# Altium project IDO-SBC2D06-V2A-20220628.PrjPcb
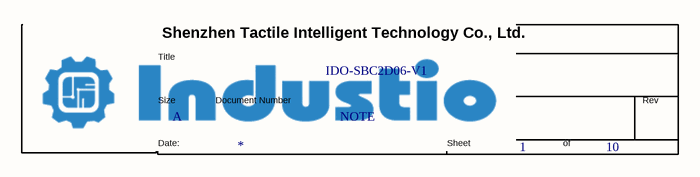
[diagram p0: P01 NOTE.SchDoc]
10 sheets, 212 parts. Net scope: global (net labels, ports and power ports of the same name join across sheets).
Sheets:
  P01 NOTE.SchDoc
  P02 POWER TREE.SchDoc
  P03 BLOCK.SchDoc
  P04 POWER_SUPPLY.SchDoc
  P06 USB_SD.SchDoc
  P07 ETHERNET.SchDoc
  P08 LCD_TP.SchDoc
  P09 AUDIO.SchDoc
  P10 Debug_RS485_RS232.SchDoc
  P05 2D02.SchDoc

## Sheet P01 NOTE.SchDoc
size 420 x 297 mm

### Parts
(Parts that share a designator on the sheet are numbered #1, #2 ... from top to bottom, then left to right.)
*#1  Page Count: 10  Page Number: 1  Page Size: A  Title: IDO-SBC2D06-V1  Doc: NOTE  (hidden comment: TitleBlock1)  (graphical)

## Sheet P02 POWER TREE.SchDoc
size 420 x 297 mm
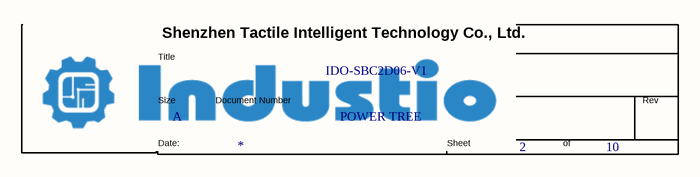
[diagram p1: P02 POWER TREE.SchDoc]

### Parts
(Parts that share a designator on the sheet are numbered #1, #2 ... from top to bottom, then left to right.)
*#2  Page Count: 10  Page Number: 2  Page Size: A  Title: IDO-SBC2D06-V1  Doc: POWER TREE  (hidden comment: TitleBlock1)  (graphical)

## Sheet P03 BLOCK.SchDoc
size 420 x 297 mm
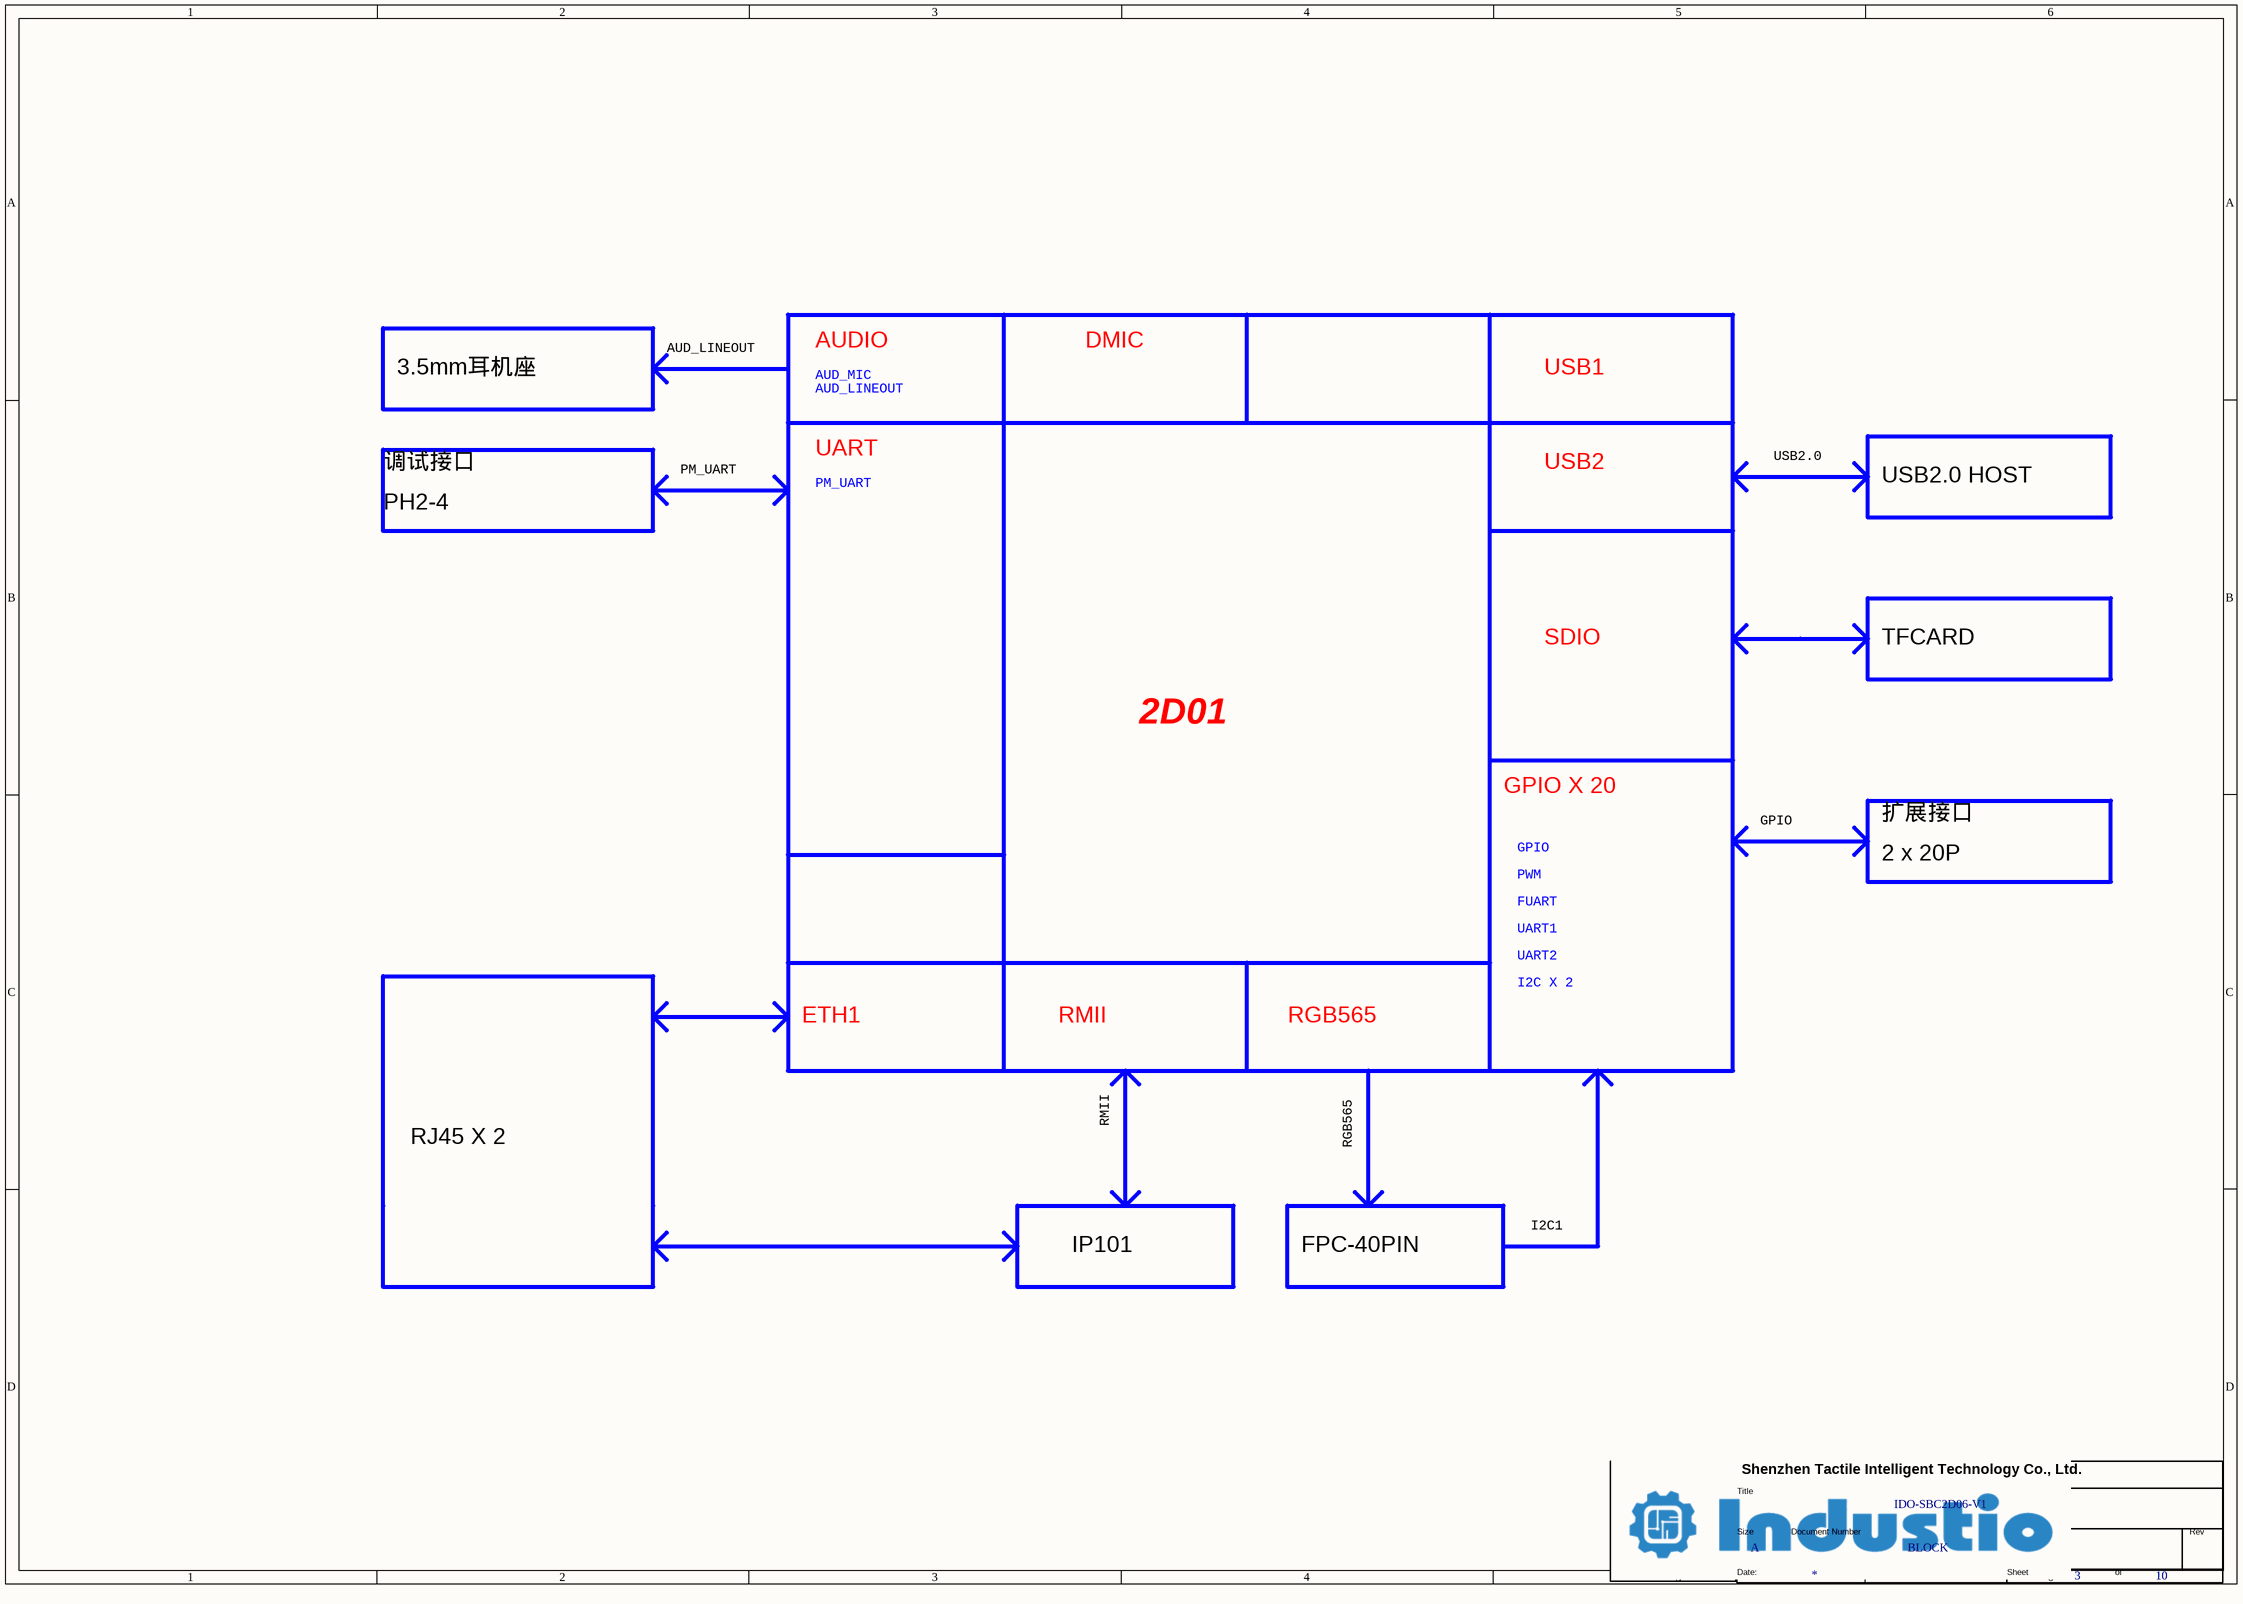
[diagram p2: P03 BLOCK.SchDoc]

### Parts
(Parts that share a designator on the sheet are numbered #1, #2 ... from top to bottom, then left to right.)
*#3  Page Count: 10  Page Number: 3  Page Size: A  Title: IDO-SBC2D06-V1  Doc: BLOCK  (hidden comment: TitleBlock1)  (graphical)

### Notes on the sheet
- 3.5mm耳机座
- AUD_LINEOUT
- AUDIO
- AUD_MIC
- DMIC
- USB1
- UART
- USB2.0
- 调试接口
- PH2-4
- PM_UART
- USB2
- USB2.0 HOST
- SDIO
- TFCARD
- 2D01
- GPIO X 20
- GPIO
- 扩展接口
- 2 x 20P
- PWM
- FUART
- UART1
- I2C X 2
- UART2
- ETH1
- RMII
- RGB565
- RJ45 X 2
- IP101
- FPC-40PIN
- I2C1

## Sheet P04 POWER_SUPPLY.SchDoc
size 420 x 297 mm
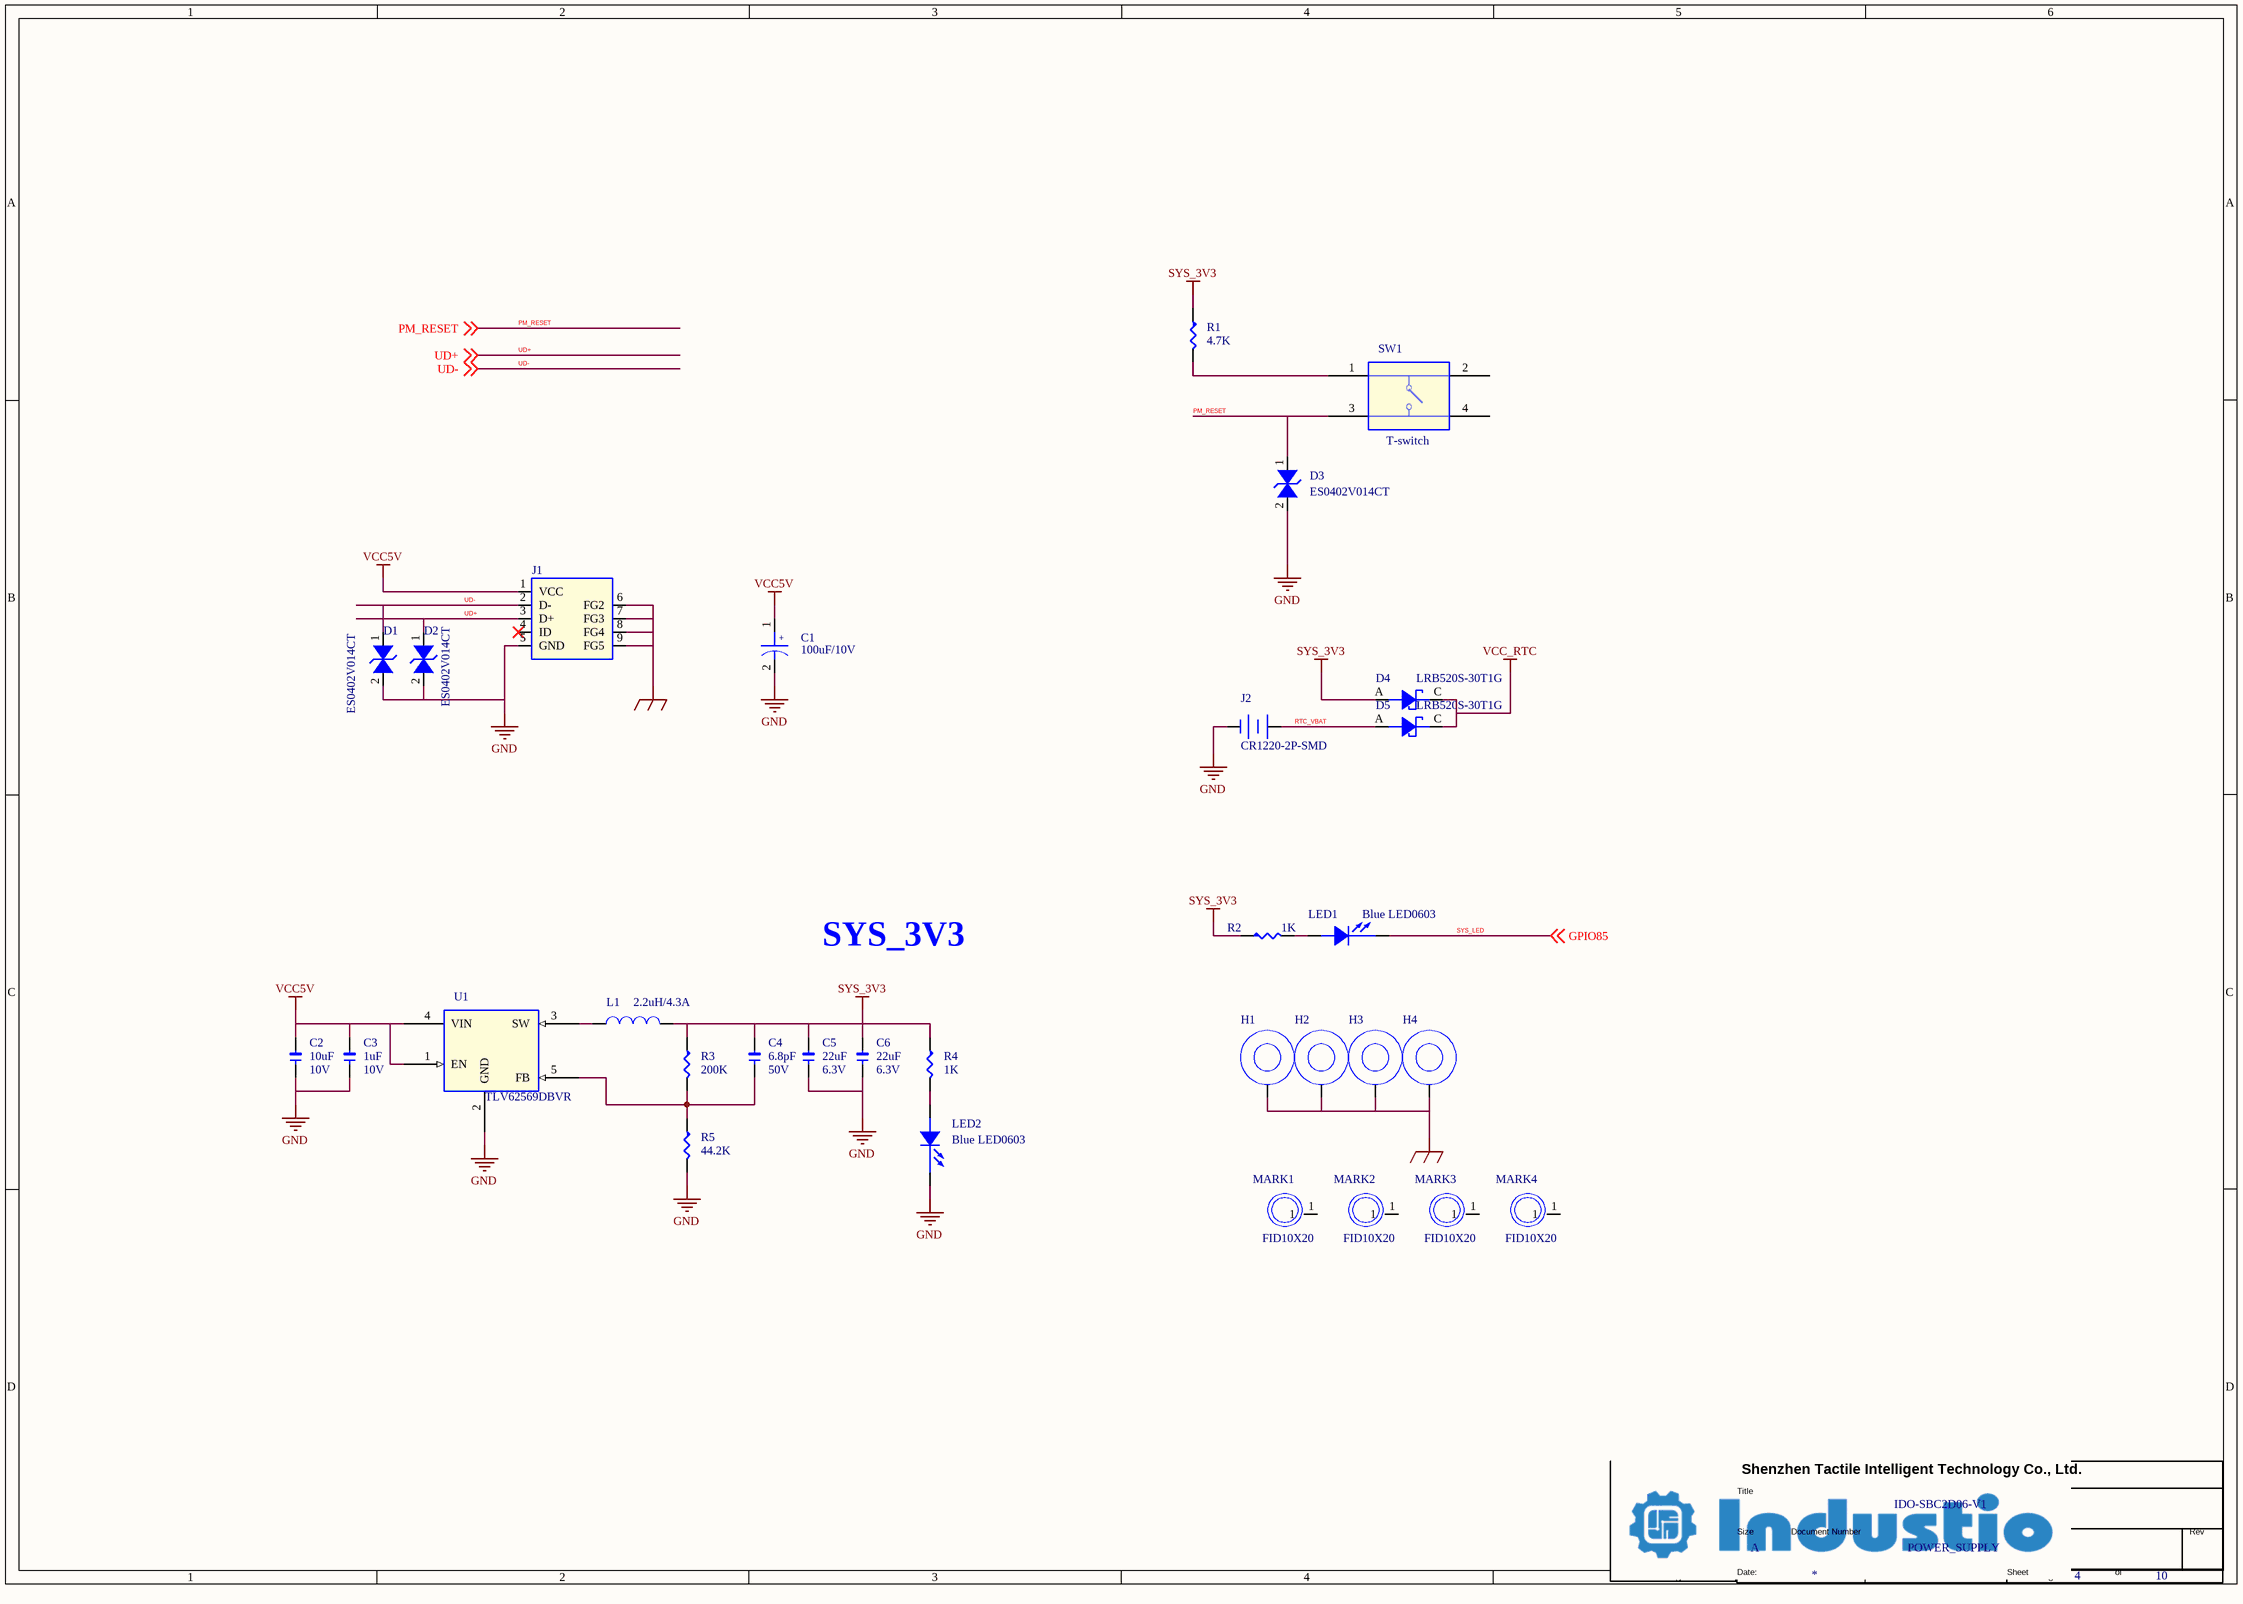
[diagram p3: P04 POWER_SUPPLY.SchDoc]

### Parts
(Parts that share a designator on the sheet are numbered #1, #2 ... from top to bottom, then left to right.)
*#4  Page Count: 10  Page Number: 4  Page Size: A  Title: IDO-SBC2D06-V1  Doc: POWER_SUPPLY  (hidden comment: TitleBlock1)  (graphical)
C1  100uF/10V  [CAPAE530X540]
C2  10uF  DSC2: 10V  [1206]
C3  1uF  DSC2: 10V  [1206]
C4  6.8pF  DSC2: 50V  [1206]
C5  22uF  DSC2: 6.3V  [1206]
C6  22uF  DSC2: 6.3V  [1206]
D1  ES0402V014CT  [V0402]
D2  ES0402V014CT  [V0402]
D3  ES0402V014CT  [V0402]
D4  LRB520S-30T1G  [SOD523]
D5  LRB520S-30T1G  [SOD523]
H1  HOLE  [MTG300_600]  (value not drawn)
H2  HOLE  [MTG300_600]  (value not drawn)
H3  HOLE  [MTG300_600]  (value not drawn)
H4  HOLE  [MTG300_600]  (value not drawn)
J1  MicroUSB  [MICROUSB-5SB]  (value not drawn)
J2  CR1220-2P-SMD  [CR1220-2P-SMD]
L1  2.2uH/4.3A  [L4040]
LED1  Blue LED0603  [LED0603]
LED2  Blue LED0603  [LED0603]
MARK1  FID10X20  [MARK]
MARK2  FID10X20  [MARK]
MARK3  FID10X20  [MARK]
MARK4  FID10X20  [MARK]
R1  4.7K  [R0402L]
R2  1K  [R0402L]
R3  200K  [R0402L]
R4  1K  [R0402L]
R5  44.2K  [R0402L]
SW1  T-switch  [PB-4P-S-4_5x4_5]
U1  TLV62569DBVR  [SOT23-5]

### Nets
GND: C1.2 C2.1 C3.1 C5.1 C6.1 D1.2(I/O1) D2.2(I/O1) D3.2(I/O1) J1.5(GND) J2.2(-) LED2.C(CATHODE) R5.2 U1.2(GND)
GND_EARTH: H1.1 H2.1 H3.1 H4.1 J1.6(FG2) J1.7(FG3) J1.8(FG4) J1.9(FG5)
SYS_3V3: C4.2 C5.2 C6.2 D4.A L1.2 R1.1 R2.1 R3.1 R4.1
VCC5V: C1.1 C2.2 C3.2 J1.1(VCC) U1.1(EN) U1.4(VIN)
VCC_RTC: D4.C D5.C
GPIO85: LED1.C(CATHODE) ; off-sheet GPIO85  [also labelled SYS_LED]
PM_RESET: D3.1(I/O2) SW1.3 ; off-sheet PM_RESET
RTC_VBAT: D5.A J2.1(+)
UD+: D2.1(I/O2) J1.3(D+) ; off-sheet UD+
UD-: D1.1(I/O2) J1.2(D-) ; off-sheet UD-
NetC4_1: C4.1 R3.2 R5.1 U1.5(FB)
NetL1_1: L1.1 U1.3(SW)
NetLED1_A: LED1.A(ANODE) R2.2
NetLED2_A: LED2.A(ANODE) R4.2
NetR1_2: R1.2 SW1.1

Not connected (* = marked no-connect by the designer): J1 4(ID)*; MARK1 1; MARK2 1; MARK3 1; MARK4 1; SW1 2 4

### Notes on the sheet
- SYS_3V3

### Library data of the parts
C1 = C-AL-SMD: Part Number: C020302140004; Part Name: 贴片铝电容; Manufacture: 先科¦立隆¦三莹; DSC1: ±20%; DSC2: 10V; DSC3: 低阻抗; DSC4: 2000H; DSC5: -55~105 ℃; DSC6: SMD,5x5.4mm; DSC7: LZ1A101M-CRD54(ST); ID: 4
C2 = C-0603: Part Number: C020102120071; Part Name: 贴片电容; Manufacture: 三星¦国巨¦村田; ERP Number: 1010200076; DSC1: ±20%; DSC3: X5R; ID: 71; PCB Footprint: C0603L
C3 = C-0402: Part Number: C020102120064; Part Name: 贴片电容; Manufacture: 三星¦国巨¦村田; ERP Number: 1010200054; DSC1: ±10%; DSC3: X5R; ID: 64; PCB Footprint: C0402L
C4 = C-0402: Manufacture: 三星¦国巨¦村田; Part Name: 贴片电容; Part Number: C020102120018; ID: 18; DSC3: C0G; DSC1: ±0.25PF; ERP Number: 1010200056; PCB Footprint: C0402L
C5 C6 = C-0603: Manufacture: 三星¦国巨¦村田; Part Name: 贴片电容; Part Number: C020102120072; ID: 72; DSC3: X5R; DSC1: ±20%; ERP Number: 1010200133; PCB Footprint: C0603L
D1-D3 = DI-ESD: ESD 0402; Manufacturer: INPAQ; Manufacture P/N: MLVG04021R0UV18; Part Number: C040502250002; Manufacture: AEM; PN Type: Varistor; ERP Number: 1010800023; DSC1: 双向; DSC2: Vdc=14V; DSC3: Vbr=300V; DSC4: Vc=30V; DSC5: Cj=0.25pF; ID: 2
D4 D5 = DI-XI-S: Manufacture: 乐山无线电; Part Name: 肖特基二级管; Part Number: C040202220002; CLASS: IC; Solder: 推荐; ID: 2; DSC4: IR=0.5uA; DSC3: VF=350mV/10mA; DSC2: IF=200mA; DSC1: VR=30V
J1 = J-MicroUSB_0: Part Name: USB连接器; Part Number: J060102960001; ID: 1; DSC4: U-F-M5DD-Y-L(韩荣); DSC3: 卧贴; DSC2: 7.6*5.6mm; DSC1: MicroUSB 5S B TYPE 四脚全插牛角型短针 耐高温
J2 = RTC-CR1220-2P-SMD: Part Number: J100303030001; Part Name: 电池座; ERP Number: 1040100045; DSC1: CR1220电池座 贴片 双定位柱; DSC3: 贴片; ID: 4
L1 = L-IND: Part Name: 功率电感; Part Number: C060202340020; Manufacture: 顺络; ERP Number: 1010200404; DSC1: ±20%; DSC2: Isat=6.1A; DSC3: Irms=4.3A; DSC4: 48mΩ; DSC5: 4.0*4.0*2.0mm; DSC6: WPN4020H2R2MT(顺络); ID: 20
LED1 LED2 = D-LED0603: Part Number: C140202660004; Part Name: LED; ERP Number: 1010200068; DSC1: 蓝色LED，SMD,0603，VF=3V; DSC2: NCD0603B1(国星光电); DSC3: 19-217/BHC-ZL1M2RY/3T(亿光); ID: 8
MARK1-MARK4 = MTG240_600_NPH_0: DSC2: 孔径2.4mm; DSC1: 禁止布线层直径=6mm; Type Name: 无铜固定孔; ID: 11
R1 = R-0402: Part Number: C011002080818; Part Name: 贴片电阻; ID: 818; DSC2: 1/16W; DSC1: ±1%; ERP Number: 1010200445
R2 R4 = R-0402: Part Number: C011002080742; Part Name: 贴片电阻; ID: 742; DSC2: 1/16W; DSC1: ±1%; ERP Number: 1010200113
R3 = R-0402: Part Name: 贴片电阻; Part Number: C011002081009; ERP Number: 1010200139; DSC1: ±1%; DSC2: 1/16W; ID: 1,009
R5 = R-0402: Part Name: 贴片电阻; Part Number: C011002080931; ERP Number: 1010200256; DSC1: ±1%; DSC2: 1/16W; ID: 931
SW1 = SW-TS4550TP: Part Name: 轻触开关; Part Number: C180102690001; ID: 1; DSC4: TS-1009S-05026(讯普); DSC3: TS4550TP(首韩); DSC2: SMD,4.5*4.5*5mm; DSC1: 轻触开关,四脚贴片,立贴
U1 = U-TLV62569DBVR: Manufacture: TI; Part Number: C070202410003; Part Name: DCDC; ID: 3; Solder: 推荐; DSC7: 同步降压 轻载效率 低Iq; DSC6: 1.5MHz; DSC5: 0.95; DSC4: Vfb=0.6V; DSC3: Io=2A; DSC2: Vo=0.6-5.5V; DSC1: Vi=2.5-5.5V

## Sheet P06 USB_SD.SchDoc
size 420 x 297 mm
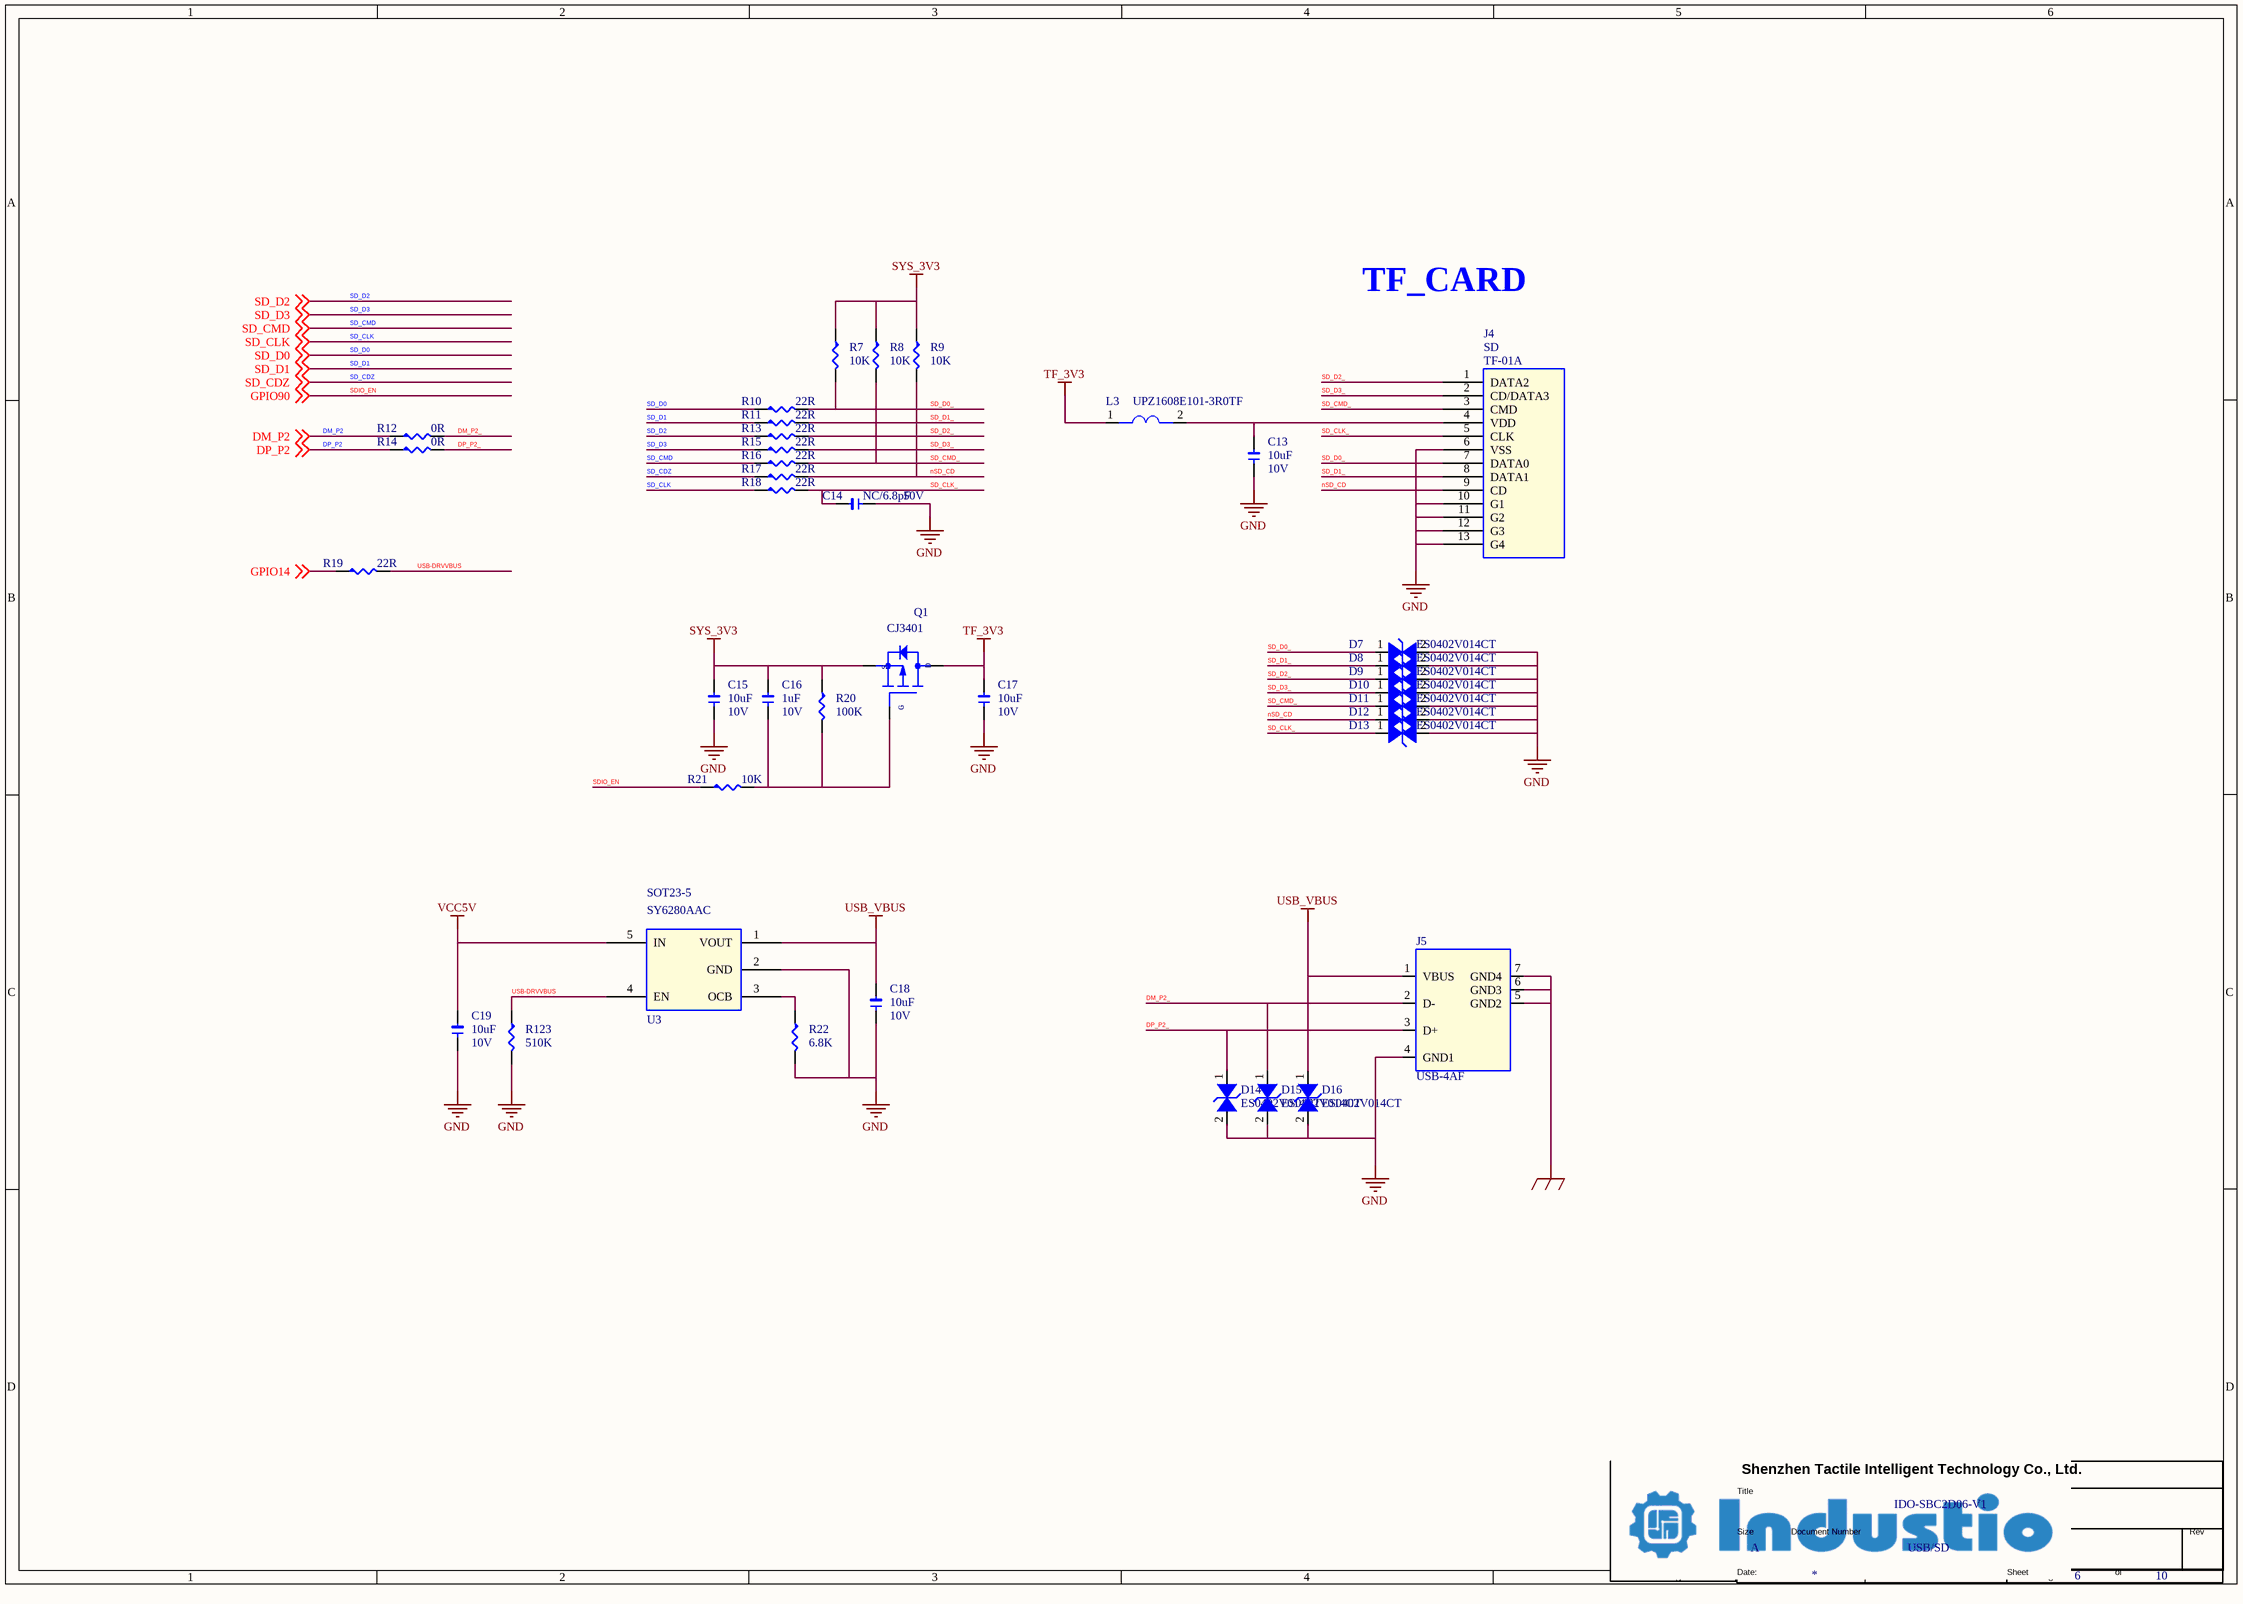
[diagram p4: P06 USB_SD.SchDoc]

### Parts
(Parts that share a designator on the sheet are numbered #1, #2 ... from top to bottom, then left to right.)
*#5  Page Count: 10  Page Number: 6  Page Size: A  Title: IDO-SBC2D06-V1  Doc: USB/SD  (hidden comment: TitleBlock1)  (graphical)
C13  10uF  DSC2: 10V  [1206]
C14  NC/6.8pF  DSC2: 50V  [1206]
C15  10uF  DSC2: 10V  [1206]
C16  1uF  DSC2: 10V  [1206]
C17  10uF  DSC2: 10V  [1206]
C18  10uF  DSC2: 10V  [1206]
C19  10uF  DSC2: 10V  [1206]
D7  ES0402V014CT  [V0402]
D8  ES0402V014CT  [V0402]
D9  ES0402V014CT  [V0402]
D10  ES0402V014CT  [V0402]
D11  ES0402V014CT  [V0402]
D12  ES0402V014CT  [V0402]
D13  ES0402V014CT  [V0402]
D14  ES0402V014CT  [V0402]
D15  ES0402V014CT  [V0402]
D16  ES0402V014CT  [V0402]
J4  SD  [TF-01A]
J5  USB-4AF  [USB-4AF-DIP-3W]
L3  UPZ1608E101-3R0TF  [L0603]
Q1  CJ3401  [SOT23]
R7  10K  [R0402L]
R8  10K  [R0402L]
R9  10K  [R0402L]
R10  22R  [R0402L]
R11  22R  [R0402L]
R12  0R  [R0402L]
R13  22R  [R0402L]
R14  0R  [R0402L]
R15  22R  [R0402L]
R16  22R  [R0402L]
R17  22R  [R0402L]
R18  22R  [R0402L]
R19  22R  [R0402L]
R20  100K  [R0402L]
R21  10K  [R0402L]
R22  6.8K  [R0402L]
R123  510K  [R0402L]
U3  SY6280AAC  [SOT23-5]

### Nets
GND: C13.1 C14.1 C15.1 C17.1 C18.1 C19.1 D7.2(I/O1) D8.2(I/O1) D9.2(I/O1) D10.2(I/O1) D11.2(I/O1) D12.2(I/O1) D13.2(I/O1) D14.2(I/O1) D15.2(I/O1) D16.2(I/O1) J4.6(VSS) J4.10(G1) J4.11(G2) J4.12(G3) J4.13(G4) J5.4(GND1) R22.2 R123.2 U3.2(GND)
GND_EARTH: J5.5(GND2) J5.6(GND3) J5.7(GND4)
SYS_3V3: C15.2 C16.2 Q1.2(SOURCE) R7.1 R8.1 R9.1 R20.1
TF_3V3: C17.2 L3.1 Q1.3(DRAIN)
USB_VBUS: C18.2 D16.1(I/O2) J5.1(VBUS) U3.1(VOUT)
VCC5V: C19.2 U3.5(IN)
DM_P2: R12.1 ; off-sheet DM_P2
DM_P2_: D15.1(I/O2) J5.2(D-) R12.2
DP_P2: R14.1 ; off-sheet DP_P2
DP_P2_: D14.1(I/O2) J5.3(D+) R14.2
GPIO14: R19.1 ; off-sheet GPIO14
GPIO90: R21.1 ; off-sheet GPIO90  [also labelled SDIO_EN]
nSD_CD: D12.1(I/O2) J4.9(CD) R9.2 R17.2
SD_CDZ: R17.1 ; off-sheet SD_CDZ
SD_CLK: R18.1 ; off-sheet SD_CLK
SD_CLK_: C14.2 D13.1(I/O2) J4.5(CLK) R18.2
SD_CMD: R16.1 ; off-sheet SD_CMD
SD_CMD_: D11.1(I/O2) J4.3(CMD) R8.2 R16.2
SD_D0: R10.1 ; off-sheet SD_D0
SD_D0_: D7.1(I/O2) J4.7(DATA0) R7.2 R10.2
SD_D1: R11.1 ; off-sheet SD_D1
SD_D1_: D8.1(I/O2) J4.8(DATA1) R11.2
SD_D2: R13.1 ; off-sheet SD_D2
SD_D2_: D9.1(I/O2) J4.1(DATA2) R13.2
SD_D3: R15.1 ; off-sheet SD_D3
SD_D3_: D10.1(I/O2) J4.2(CD/DATA3) R15.2
USB-DRVVBUS: R19.2 R123.1 U3.4(EN)
NetC13_2: C13.2 J4.4(VDD) L3.2
NetC16_1: C16.1 Q1.1(GATE) R20.2 R21.2
NetR22_1: R22.1 U3.3(OCB)

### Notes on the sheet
- TF_CARD

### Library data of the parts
C13 C15 C17 C18 = C-0603: Manufacture: 三星¦国巨¦村田; Part Name: 贴片电容; Part Number: C020102120071; ID: 71; DSC3: X5R; DSC1: ±20%; ERP Number: 1010200076; PCB Footprint: C0603L
C14 = C-0402: as C4 on sheet P04 POWER_SUPPLY
C16 = C-0402: Manufacture: 三星¦国巨¦村田; Part Name: 贴片电容; Part Number: C020102120064; ID: 64; DSC3: X5R; DSC1: ±10%; ERP Number: 1010200054; PCB Footprint: C0402L
C19 = C-0603: as C2 on sheet P04 POWER_SUPPLY
D7-D11 = DI-ESD: as D1 on sheet P04 POWER_SUPPLY
D12-D16 = DI-ESD: ESD 0402; Manufacturer: INPAQ; Manufacture P/N: MLVG04021R0UV18; Part Number: C040502250002; Manufacture: AEM; PN Type: Varistor; ID: 2; DSC5: Cj=0.25pF; DSC4: Vc=30V; DSC3: Vbr=300V; DSC2: Vdc=14V; DSC1: 双向; ERP Number: 1010800023
J4 = J-TF-01A: Part Name: SD卡座; Part Number: J080102980002; ID: 2; DSC4: TF-01A(韩荣); DSC3: 贴片; DSC1: TF卡座 自弹式
J5 = J-USB-4AF-DIP-W-3_1: micro USB连接器; Part Number: J060102960007; DSC1: USB AF 90度 侧插 铁壳短体10.4 无卷边 白胶; DSC2: 10.4*5.7mm*13.1; DSC3: 通孔弯针; DSC4: C42684(LC); ID: 7
L3 = FB-0603: SMD Multilayer Ferrite Chip Bead,3A,30Ohm,0.03R; Part Number: C060502370005; Manufacture P/N: PZ1608D300-3R0TF; Manufacture2 P/N: PBY160808T-400Y-N; Manufacturer: SUNLORD; Part Name: 贴片磁珠; Manufacture: 顺络; PN Type: SMD FERRITE BEAD; ERP Number: 1010200207; DSC1: 100Ω@100MHz; DSC3: DCR=30mΩ; DSC4: 电源线; ID: 5
Q1 = P-MOS: Manufacture: 长电; Part Number: C030202190001; ID: 1; DSC5: pd=350mW; DSC4: Vgs=±12V; DSC3: Vgs(th)=1.3V; DSC2: Id=-4.2A; DSC1: Vds=-30V; ERP Number: 1010800001
R7-R9 = R-0402: Part Number: C011002080856; Part Name: 贴片电阻; ID: 856; DSC2: 1/16W; DSC1: ±1%; ERP Number: 1010200140
R10 = R-0402: Part Number: C011002080552; Part Name: 贴片电阻; ID: 552; DSC2: 1/16W; DSC1: ±1%
R11 R13 R15-R19 = R-0402: Part Name: 贴片电阻; Part Number: C011002080552; DSC1: ±1%; DSC2: 1/16W; ID: 552
R12 R14 = R-0402: Part Number: C011002080413; Part Name: 贴片电阻; ID: 413; DSC2: 1/16W; DSC1: ±1%
R20 = R-0402: Part Number: C011002080976; Part Name: 贴片电阻; ID: 976; DSC2: 1/16W; DSC1: ±1%; ERP Number: 1010200137
R21 = R-0402: Part Name: 贴片电阻; Part Number: C011002080856; ERP Number: 1010200140; DSC1: ±1%; DSC2: 1/16W; ID: 856
R22 = R-0402: Part Name: 贴片电阻; Part Number: C011002080837; ERP Number: 1010200334; DSC1: ±1%; DSC2: 1/16W; ID: 837
R123 = R-0402: Part Number: C011002081059; Part Name: 贴片电阻; ID: 1,059; DSC2: 1/16W; DSC1: ±1%; ERP Number: 1010200459
U3 = U-SY6280AAC: Part Number: C070402430001; Part Name: 功率开关; Manufacture: 矽力杰; ERP Number: 1010100222; DSC1: 低能耗电源开关; DSC2: 2.4-5.5V 2A; DSC3: 80m?; DSC4: -40~85℃; ID: 1

## Sheet P07 ETHERNET.SchDoc
size 420 x 297 mm
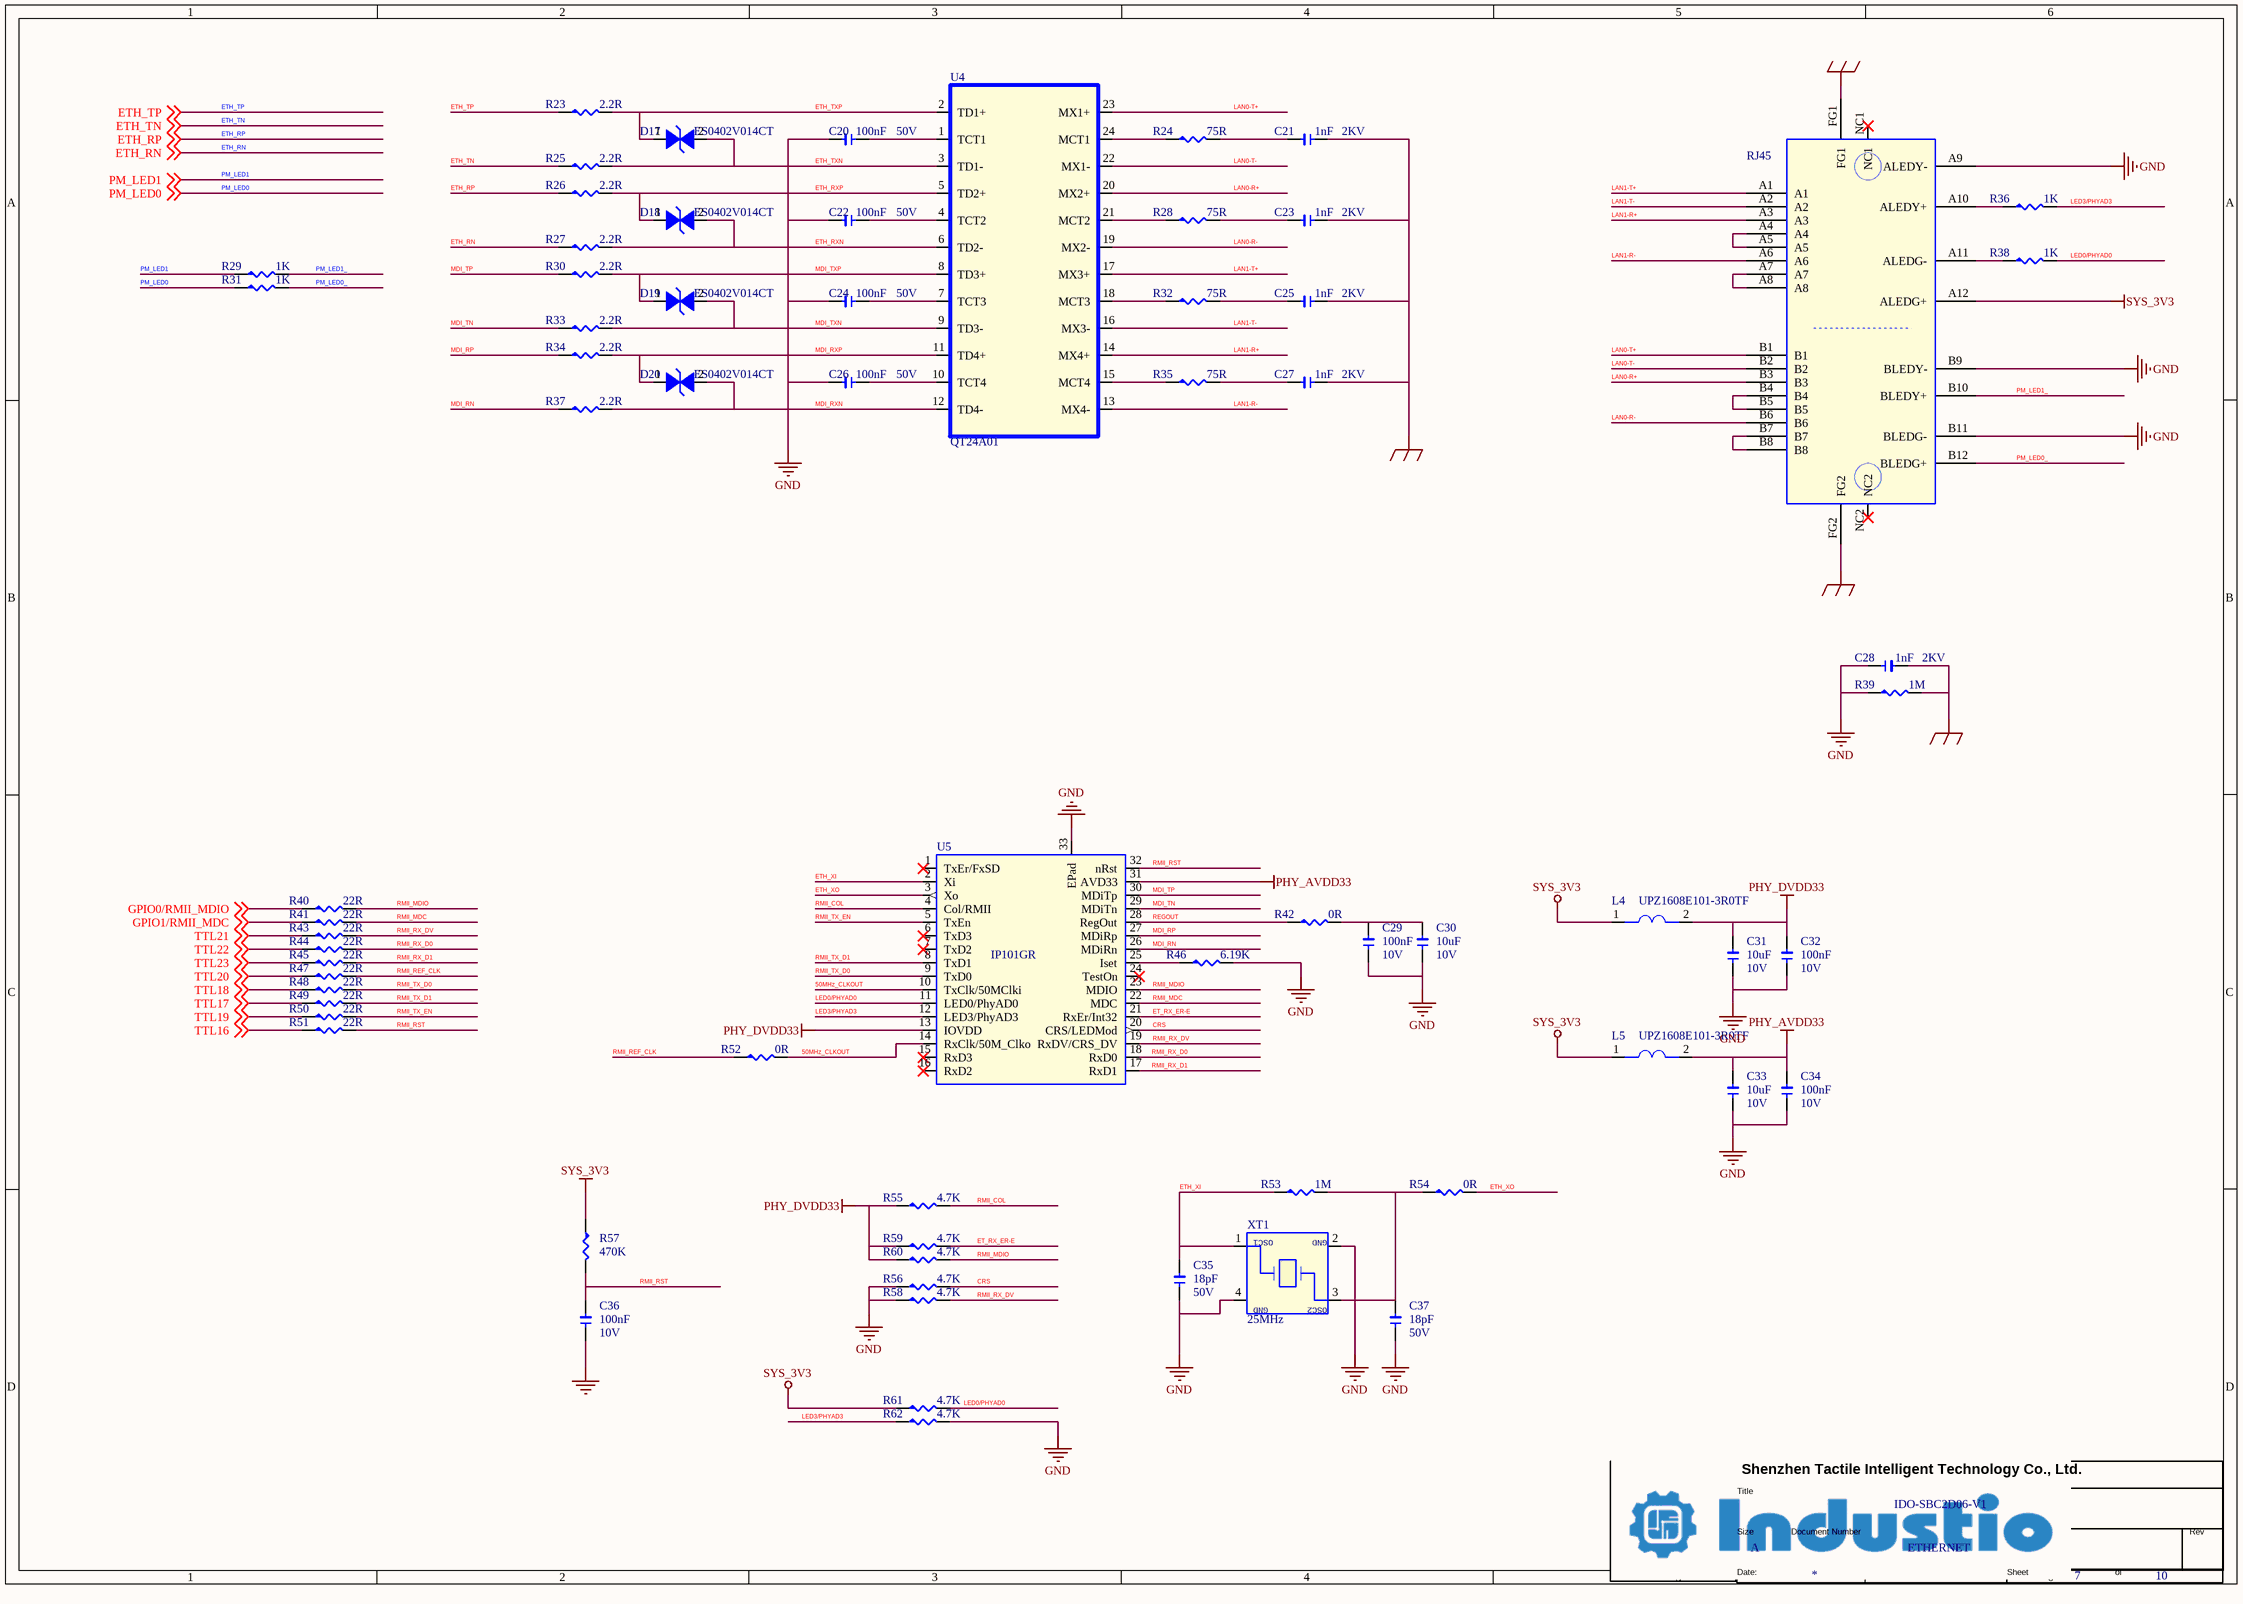
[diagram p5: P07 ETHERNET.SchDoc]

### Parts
(Parts that share a designator on the sheet are numbered #1, #2 ... from top to bottom, then left to right.)
*#6  Page Count: 10  Page Number: 7  Page Size: A  Title: IDO-SBC2D06-V1  Doc: ETHERNET  (hidden comment: TitleBlock1)  (graphical)
C20  100nF  DSC2: 50V  [1206]
C21  1nF  DSC2: 2KV  [1206]
C22  100nF  DSC2: 50V  [1206]
C23  1nF  DSC2: 2KV  [1206]
C24  100nF  DSC2: 50V  [1206]
C25  1nF  DSC2: 2KV  [1206]
C26  100nF  DSC2: 50V  [1206]
C27  1nF  DSC2: 2KV  [1206]
C28  1nF  DSC2: 2KV  [1206]
C29  100nF  DSC2: 10V  [1206]
C30  10uF  DSC2: 10V  [1206]
C31  10uF  DSC2: 10V  [1206]
C32  100nF  DSC2: 10V  [1206]
C33  10uF  DSC2: 10V  [1206]
C34  100nF  DSC2: 10V  [1206]
C35  18pF  DSC2: 50V  [1206]
C36  100nF  DSC2: 10V  [1206]
C37  18pF  DSC2: 50V  [1206]
D17  ES0402V014CT  [V0402]
D18  ES0402V014CT  [V0402]
D19  ES0402V014CT  [V0402]
D20  ES0402V014CT  [V0402]
J6  RJ45  [RJ45-1X2-8P8C-R-LED]
L4  UPZ1608E101-3R0TF  [L0603]
L5  UPZ1608E101-3R0TF  [L0603]
R23  2.2R  [R0402L]
R24  75R  [R0603L]
R25  2.2R  [R0402L]
R26  2.2R  [R0402L]
R27  2.2R  [R0402L]
R28  75R  [R0603L]
R29  1K  [R0402L]
R30  2.2R  [R0402L]
R31  1K  [R0402L]
R32  75R  [R0603L]
R33  2.2R  [R0402L]
R34  2.2R  [R0402L]
R35  75R  [R0603L]
R36  1K  [R0402L]
R37  2.2R  [R0402L]
R38  1K  [R0402L]
R39  1M  [R0805L]
R40  22R  [R0402L]
R41  22R  [R0402L]
R42  0R  [R0402L]
R43  22R  [R0402L]
R44  22R  [R0402L]
R45  22R  [R0402L]
R46  6.19K  [R0402L]
R47  22R  [R0402L]
R48  22R  [R0402L]
R49  22R  [R0402L]
R50  22R  [R0402L]
R51  22R  [R0402L]
R52  0R  [R0402L]
R53  1M  [R0402L]
R54  0R  [R0402L]
R55  4.7K  [R0402L]
R56  4.7K  [R0402L]
R57  470K  [R0402L]
R58  4.7K  [R0402L]
R59  4.7K  [R0402L]
R60  4.7K  [R0402L]
R61  4.7K  [R0402L]
R62  4.7K  [R0402L]
U4  QT24A01  [QT24A01-SOP24]
U5  IP101GR  [QFN32]
XT1  25MHz  [xtal_32x25_4p]

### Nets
GND: C20.2 C22.2 C24.2 C26.2 C28.1 C29.1 C30.1 C31.1 C32.1 C33.1 C34.1 C35.1 C36.1 C37.1 J6.A9(ALEDY-) J6.B9(BLEDY-) J6.B11(BLEDG-) R39.1 R46.2 R56.1 R58.1 R62.2 U5.33(EPad) XT1.2 XT1.4
GND_EARTH: C21.1 C23.1 C25.1 C27.1 C28.2 J6.FG1 J6.FG2 R39.2
PHY_AVDD33: C33.2 C34.2 L5.2 U5.31(AVD33)
PHY_DVDD33: C31.2 C32.2 L4.2 R55.1 R59.1 R60.1 U5.13(IOVDD)
SYS_3V3: J6.A12(ALEDG+) L4.1 L5.1 R57.1 R61.1
50MHz_CLKOUT: R52.2 U5.10(TxClk/50MClki) U5.14(RxClk/50M_Clko)
CRS: R56.2 U5.20(CRS/LEDMod)
ET_RX_ER-E: R59.2 U5.21(RxEr/Int32)
ETH_RN: R27.1 ; off-sheet ETH_RN
ETH_RP: R26.1 ; off-sheet ETH_RP
ETH_RXN: D18.2(I/O1) R27.2 U4.6(TD2-)
ETH_RXP: D18.1(I/O2) R26.2 U4.5(TD2+)
ETH_TN: R25.1 ; off-sheet ETH_TN
ETH_TP: R23.1 ; off-sheet ETH_TP
ETH_TXN: D17.2(I/O1) R25.2 U4.3(TD1-)
ETH_TXP: D17.1(I/O2) R23.2 U4.2(TD1+)
ETH_XI: C35.2 R53.1 U5.2(Xi) XT1.1
ETH_XO: R54.2 U5.3(Xo)
GPIO0/RMII_MDIO: R40.1 ; off-sheet GPIO0/RMII_MDIO
GPIO1/RMII_MDC: R41.1 ; off-sheet GPIO1/RMII_MDC
LAN0-R+: J6.B3 U4.20(MX2+)
LAN0-R-: J6.B6 U4.19(MX2-)
LAN0-T+: J6.B1 U4.23(MX1+)
LAN0-T-: J6.B2 U4.22(MX1-)
LAN1-R+: J6.A3 U4.14(MX4+)
LAN1-R-: J6.A6 U4.13(MX4-)
LAN1-T+: J6.A1 U4.17(MX3+)
LAN1-T-: J6.A2 U4.16(MX3-)
LED0/PHYAD0: R38.2 R61.2 U5.11(LED0/PhyAD0)
LED3/PHYAD3: R36.2 R62.1 U5.12(LED3/PhyAD3)
MDI_RN: R37.1 U5.26(MDiRn)
MDI_RP: R34.1 U5.27(MDiRp)
MDI_RXN: D20.2(I/O1) R37.2 U4.12(TD4-)
MDI_RXP: D20.1(I/O2) R34.2 U4.11(TD4+)
MDI_TN: R33.1 U5.29(MDiTn)
MDI_TP: R30.1 U5.30(MDiTp)
MDI_TXN: D19.2(I/O1) R33.2 U4.9(TD3-)
MDI_TXP: D19.1(I/O2) R30.2 U4.8(TD3+)
PM_LED0: R31.1 ; off-sheet PM_LED0
PM_LED0_: J6.B12(BLEDG+) R31.2
PM_LED1: R29.1 ; off-sheet PM_LED1
PM_LED1_: J6.B10(BLEDY+) R29.2
REGOUT: R42.1 U5.28(RegOut)
RMII_COL: R55.2 U5.4(Col/RMII)
RMII_MDC: R41.2 U5.22(MDC)
RMII_MDIO: R40.2 R60.2 U5.23(MDIO)
RMII_REF_CLK: R47.2 R52.1
RMII_RST: C36.2 R51.2 R57.2 U5.32(nRst)
RMII_RX_D0: R44.2 U5.18(RxD0)
RMII_RX_D1: R45.2 U5.17(RxD1)
RMII_RX_DV: R43.2 R58.2 U5.19(RxDV/CRS_DV)
RMII_TX_D0: R48.2 U5.9(TxD0)
RMII_TX_D1: R49.2 U5.8(TxD1)
RMII_TX_EN: R50.2 U5.5(TxEn)
TTL16: R51.1 ; off-sheet TTL16
TTL17: R49.1 ; off-sheet TTL17
TTL18: R48.1 ; off-sheet TTL18
TTL19: R50.1 ; off-sheet TTL19
TTL20: R47.1 ; off-sheet TTL20
TTL21: R43.1 ; off-sheet TTL21
TTL22: R44.1 ; off-sheet TTL22
TTL23: R45.1 ; off-sheet TTL23
NetC20_1: C20.1 U4.1(TCT1)
NetC21_2: C21.2 R24.2
NetC22_1: C22.1 U4.4(TCT2)
NetC23_2: C23.2 R28.2
NetC24_1: C24.1 U4.7(TCT3)
NetC25_2: C25.2 R32.2
NetC26_1: C26.1 U4.10(TCT4)
NetC27_2: C27.2 R35.2
NetC29_2: C29.2 C30.2 R42.2
NetC37_2: C37.2 R53.2 R54.1 XT1.3
NetJ6_A4: J6.A4 J6.A5
NetJ6_A7: J6.A7 J6.A8
NetJ6_A10: J6.A10(ALEDY+) R36.1
NetJ6_A11: J6.A11(ALEDG-) R38.1
NetJ6_B4: J6.B4 J6.B5
NetJ6_B7: J6.B7 J6.B8
NetR24_1: R24.1 U4.24(MCT1)
NetR28_1: R28.1 U4.21(MCT2)
NetR32_1: R32.1 U4.18(MCT3)
NetR35_1: R35.1 U4.15(MCT4)
NetR46_1: R46.1 U5.25(Iset)

Not connected (* = marked no-connect by the designer): J6 NC1* NC2*; U5 1(TxEr/FxSD)* 6(TxD3)* 7(TxD2)* 15(RxD3)* 16(RxD2)* 24(TestOn)*

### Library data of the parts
C20 C24 C26 = C-0402: Part Number: C020102120061; Part Name: 贴片电容; Manufacture: 三星¦国巨¦村田; ERP Number: 1010200128; DSC1: ±10%; DSC3: X7R; ID: 61; PCB Footprint: C0402L
C21 C27 C28 = C-1206: Part Number: C020102120077; Part Name: 贴片电容; Manufacture: 三星¦国巨¦村田; ERP Number: 1010200094; DSC1: ±10%; DSC3: X7R; ID: 77; PCB Footprint: C1206L
C22 = C-0402: Manufacture: 三星¦国巨¦村田; Part Name: 贴片电容; Part Number: C020102120061; ID: 61; DSC3: X7R; DSC1: ±10%; ERP Number: 1010200128; PCB Footprint: C0402L
C23 C25 = C-1206: Manufacture: 三星¦国巨¦村田; Part Name: 贴片电容; Part Number: C020102120077; ID: 77; DSC3: X7R; DSC1: ±10%; ERP Number: 1010200094; PCB Footprint: C1206L
C29 C34 = C-0402: Manufacture: 三星¦国巨¦村田; Part Name: 贴片电容; Part Number: C020102120060; ID: 60; DSC3: X7R; DSC1: ±10%; PCB Footprint: C0402L
C30 C31 C33 = C-0603: as C2 on sheet P04 POWER_SUPPLY
C32 C36 = C-0402: Part Number: C020102120060; Part Name: 贴片电容; Manufacture: 三星¦国巨¦村田; DSC1: ±10%; DSC3: X7R; ID: 60; PCB Footprint: C0402L
C35 = C-0402: Part Number: C020102120027; Part Name: 贴片电容; Manufacture: 三星¦国巨¦村田; ERP Number: 1010200091; DSC1: ±5%; DSC3: C0G; ID: 27; PCB Footprint: C0402L
C37 = C-0402: Manufacture: 三星¦国巨¦村田; Part Name: 贴片电容; Part Number: C020102120027; ID: 27; DSC3: C0G; DSC1: ±5%; ERP Number: 1010200091; PCB Footprint: C0402L
D17 D20 = DI-ESD: as D1 on sheet P04 POWER_SUPPLY
D18 D19 = DI-ESD: as D12 on sheet P06 USB_SD
J6 = J-RJ45-1X2: Part Number: J120103060002; ID: 2; DSC3: 通孔弯针; DSC1: RJ45网口连接器,带LED灯,8p8c,横向并排双座,黑色,后脚,4.57,铜壳,无弹片
L4 L5 = FB-0603: SMD Multilayer Ferrite Chip Bead,3A,30Ohm,0.03R; Part Number: C060502370005; Manufacture P/N: PZ1608D300-3R0TF; Manufacture2 P/N: PBY160808T-400Y-N; Manufacturer: SUNLORD; Manufacture: 顺络; Part Name: 贴片磁珠; PN Type: SMD FERRITE BEAD; ID: 5; DSC4: 电源线; DSC3: DCR=30mΩ; DSC1: 100Ω@100MHz; ERP Number: 1010200207
R23 R30 = R-0402: Part Name: 贴片电阻; Part Number: C011002080453; DSC1: ±1%; DSC2: 1/16W; ID: 453
R24 R28 R32 R35 = R-0603: Part Name: 贴片电阻; Part Number: C011002081348; ERP Number: 1010200269; DSC1: ±1%; DSC2: 1/10W; ID: 1,348
R25-R27 R33 R34 R37 = R-0402: Part Number: C011002080453; Part Name: 贴片电阻; ID: 453; DSC2: 1/16W; DSC1: ±1%
R29 R31 = R-0402: Part Name: 贴片电阻; Part Number: C011002080742; ERP Number: 1010200113; DSC1: ±1%; DSC2: 1/16W; ID: 742
R36 R38 = R-0402: as R2 on sheet P04 POWER_SUPPLY
R39 = R-0805: Part Name: 贴片电阻; Part Number: C011002081864; ERP Number: 1010200447; DSC1: ±1%; DSC2: 1/8W; ID: 1,864
R40 R41 R43-R45 R47 R48 R50 = R-0402: as R10 on sheet P06 USB_SD
R42 = R-0402: Part Name: 贴片电阻; Part Number: C011002080413; DSC1: ±1%; DSC2: 1/16W; ID: 413
R46 = R-0402: Part Number: C011002080832; Part Name: 贴片电阻; ID: 832; DSC2: 1/16W; DSC1: ±1%; ERP Number: 1010200441
R49 R51 = R-0402: as R11 on sheet P06 USB_SD
R52 R54 = R-0402: as R12 on sheet P06 USB_SD
R53 = R-0402: Part Name: 贴片电阻; Part Number: C011002081093; ERP Number: 1010200470; DSC1: ±1%; DSC2: 1/16W; ID: 1,093
R55 = R-0402: as R1 on sheet P04 POWER_SUPPLY
R56 R58-R62 = R-0402: Part Name: 贴片电阻; Part Number: C011002080818; ERP Number: 1010200445; DSC1: ±1%; DSC2: 1/16W; ID: 818
R57 = R-0402: Part Number: C011002081055; Part Name: 贴片电阻; ID: 1,055; DSC2: 1/16W; DSC1: ±1%; ERP Number: 1010200370
U4 = U-QT24A01_0: Part Name: 网口变压器; ID: 2; ERP Number: C060702390002; DSC1: 贴片 单口千兆或双口百兆; DSC2: 0~70℃; DSC3: SMD,SOP24,15.1*7*4mm
U5 = U-IP101GR: Part Number: C100102490006; Part Name: 以太网芯片; Manufacture: IC+(九阳电子); ERP Number: 1010100239; DSC1: Single Port 10/100 MII/RMII/TP/Fiber / Fast Ethernet Transceiver; DSC2: QFN32，5mm×5mm，0.5mm Pitch; DSC3: 0℃~+70℃; ID: 6; PCB Footprint: IP101GR-VQFN-32
XT1 = XTAL-4P: Part Name: 贴片无源晶振; Part Number: C050102290006; Manufacture: 泰晶; CLASS: IC; DSC1: 40Ω; DSC2: ±10ppm; DSC3: 12pF; DSC4: -40℃~+85℃; DSC5: 3.2*2.5mm 4P; ID: 6

## Sheet P08 LCD_TP.SchDoc
size 420 x 297 mm
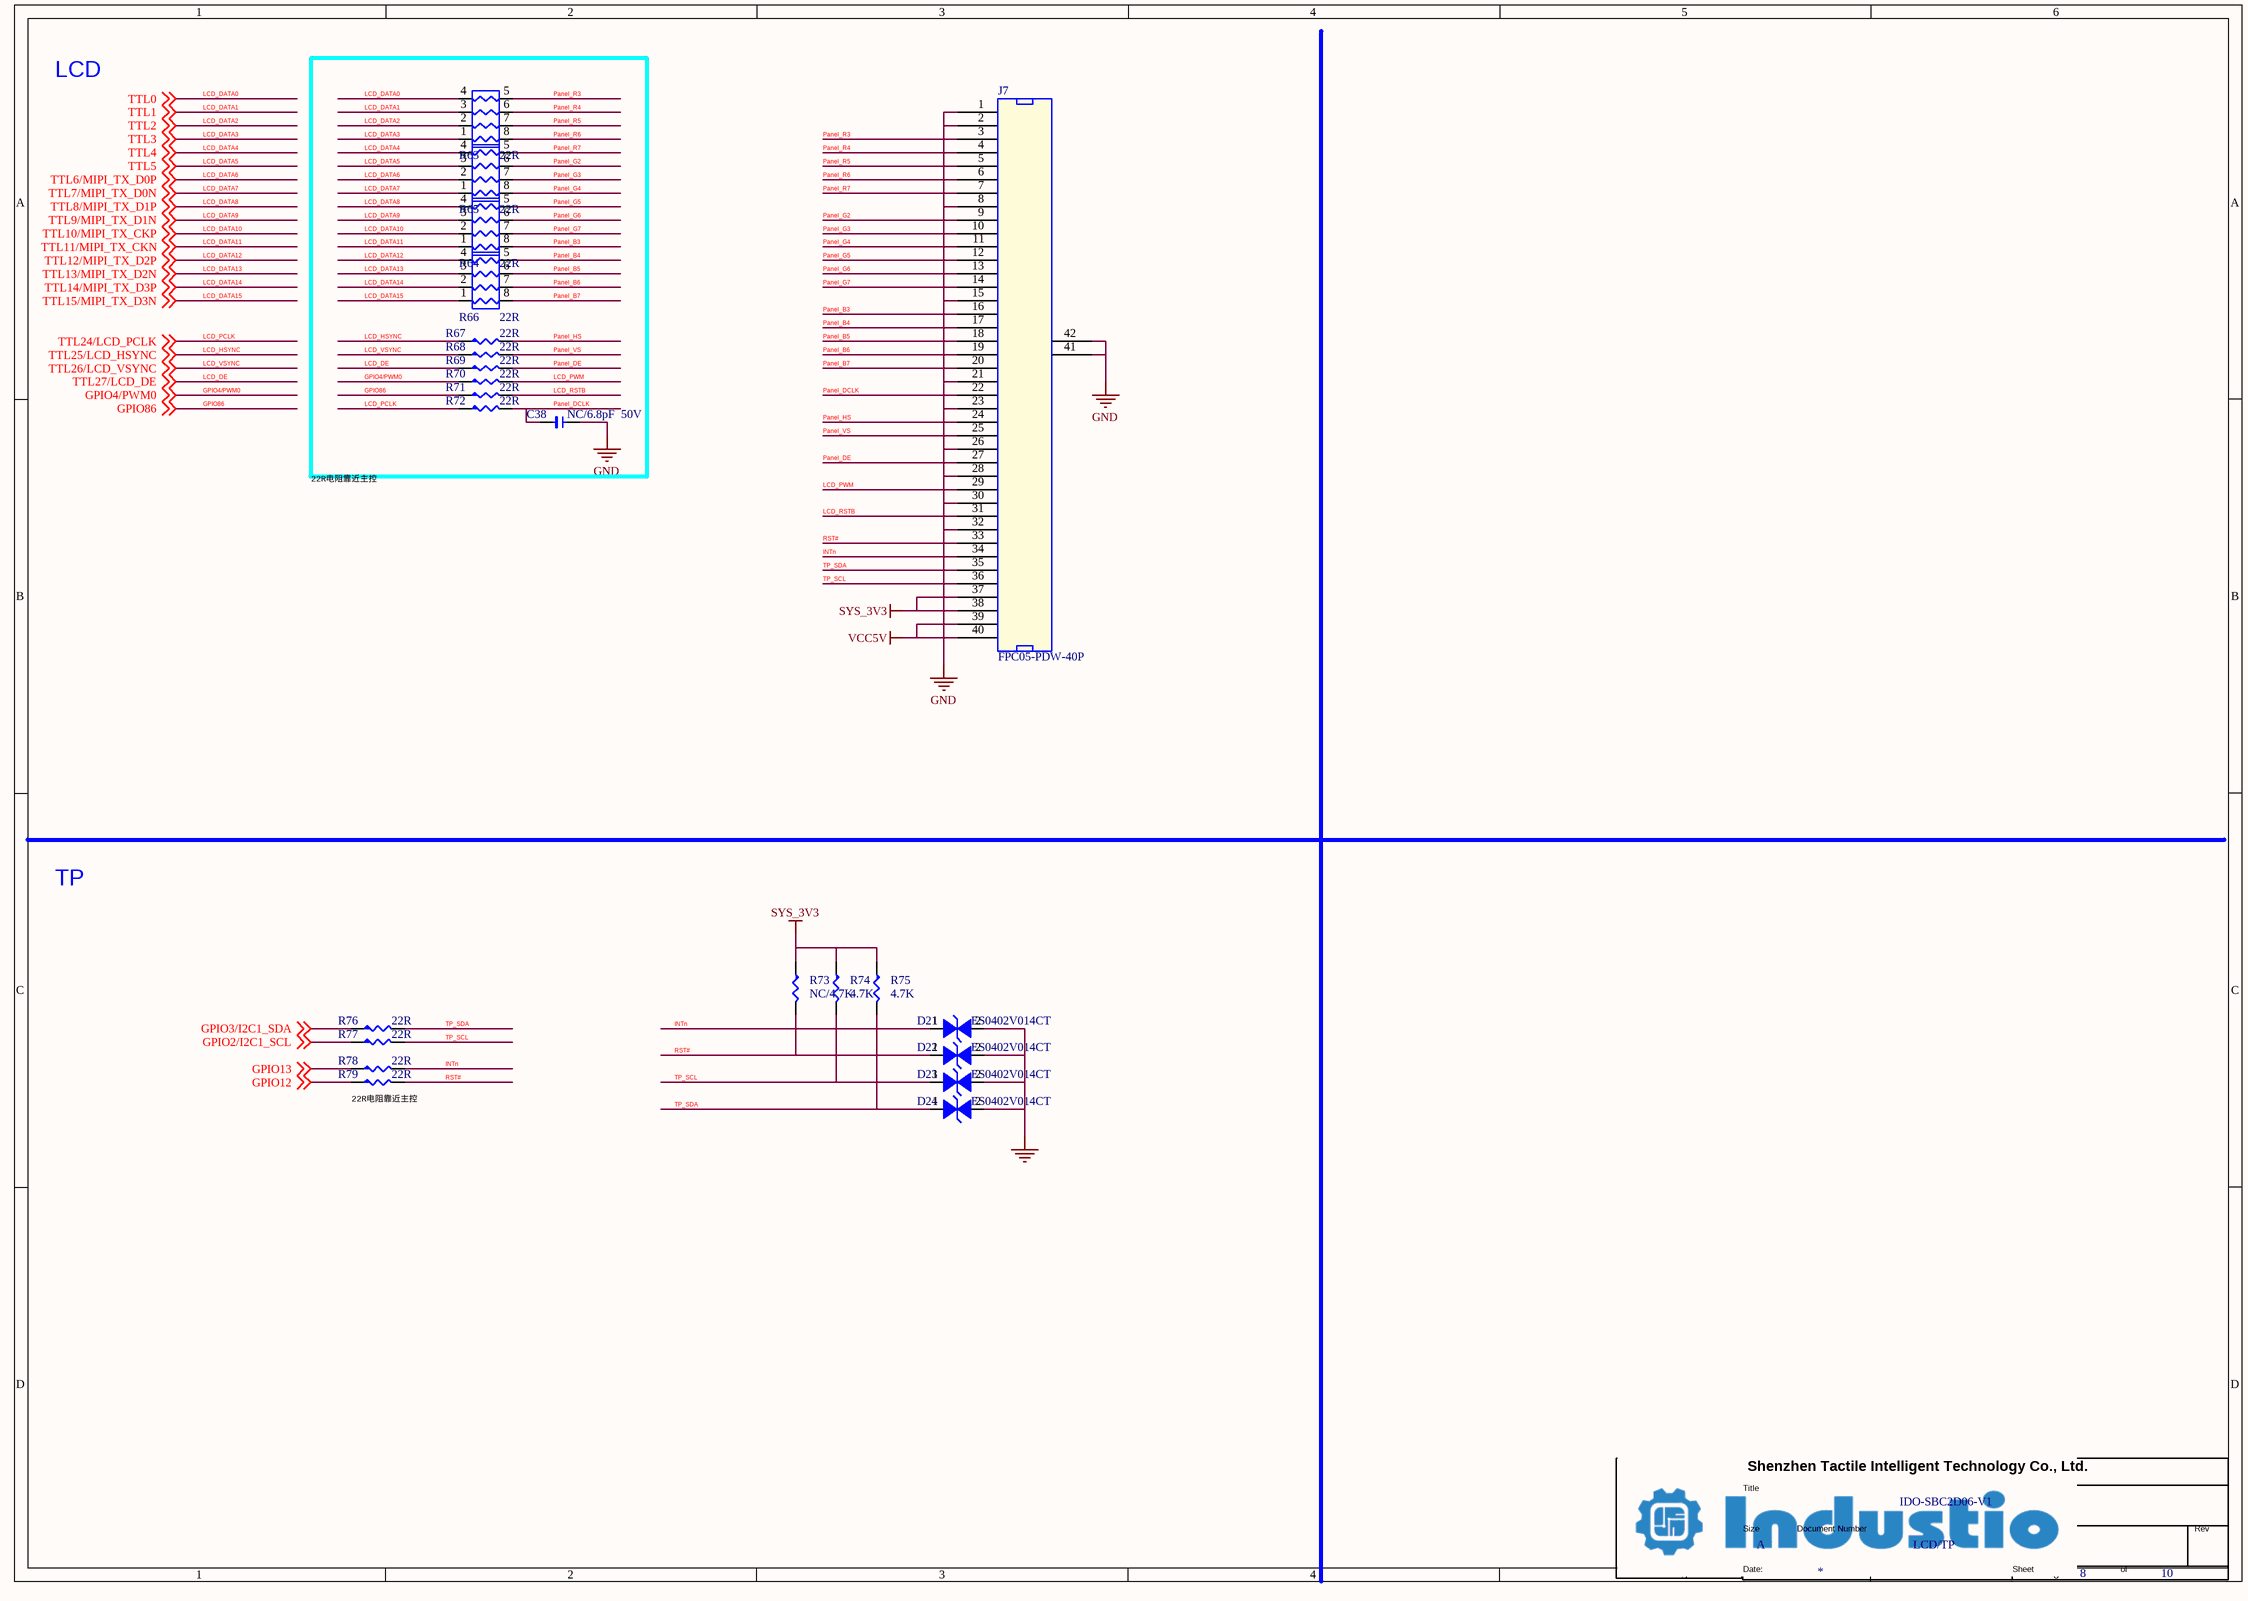
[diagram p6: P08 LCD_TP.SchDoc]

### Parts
(Parts that share a designator on the sheet are numbered #1, #2 ... from top to bottom, then left to right.)
*#7  Page Count: 10  Page Number: 8  Page Size: A  Title: IDO-SBC2D06-V1  Doc: LCD/TP  (hidden comment: TitleBlock1)  (graphical)
C38  NC/6.8pF  DSC2: 50V  [1206]
D21  ES0402V014CT  [V0402]
D22  ES0402V014CT  [V0402]
D23  ES0402V014CT  [V0402]
D24  ES0402V014CT  [V0402]
J7  FPC05-PDW-40P  [FPC05-PDW-40P]
R63  22R  [RN_0402X4]
R64  22R  [RN_0402X4]
R65  22R  [RN_0402X4]
R66  22R  [RN_0402X4]
R67  22R  [R0402L]
R68  22R  [R0402L]
R69  22R  [R0402L]
R70  22R  [R0402L]
R71  22R  [R0402L]
R72  22R  [R0402L]
R73  NC/4.7K  [R0402L]
R74  4.7K  [R0402L]
R75  4.7K  [R0402L]
R76  22R  [R0402L]
R77  22R  [R0402L]
R78  22R  [R0402L]
R79  22R  [R0402L]

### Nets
GND: C38.1 D21.2(I/O1) D22.2(I/O1) D23.2(I/O1) D24.2(I/O1) J7.1 J7.2 J7.8 J7.15 J7.21 J7.23 J7.26 J7.28 J7.30 J7.32 J7.41 J7.42
SYS_3V3: J7.37 J7.38 R73.1 R74.1 R75.1
VCC5V: J7.39 J7.40
GPIO2/I2C1_SCL: R77.1 ; off-sheet GPIO2/I2C1_SCL
GPIO3/I2C1_SDA: R76.1 ; off-sheet GPIO3/I2C1_SDA
GPIO4/PWM0: R70.1 ; off-sheet GPIO4/PWM0
GPIO12: R79.1 ; off-sheet GPIO12
GPIO13: R78.1 ; off-sheet GPIO13
GPIO86: R71.1 ; off-sheet GPIO86
INTn: D21.1(I/O2) J7.34 R78.2
LCD_DATA0: R63.4 ; off-sheet TTL0  [also labelled TTL0]
LCD_DATA1: R63.3 ; off-sheet TTL1  [also labelled TTL1]
LCD_DATA2: R63.2 ; off-sheet TTL2  [also labelled TTL2]
LCD_DATA3: R63.1 ; off-sheet TTL3  [also labelled TTL3]
LCD_DATA4: R65.4 ; off-sheet TTL4  [also labelled TTL4]
LCD_DATA5: R65.3 ; off-sheet TTL5  [also labelled TTL5]
LCD_DATA6: R65.2 ; off-sheet TTL6/MIPI_TX_D0P  [also labelled TTL6/MIPI_TX_D0P]
LCD_DATA7: R65.1 ; off-sheet TTL7/MIPI_TX_D0N  [also labelled TTL7/MIPI_TX_D0N]
LCD_DATA8: R64.4 ; off-sheet TTL8/MIPI_TX_D1P  [also labelled TTL8/MIPI_TX_D1P]
LCD_DATA9: R64.3 ; off-sheet TTL9/MIPI_TX_D1N  [also labelled TTL9/MIPI_TX_D1N]
LCD_DATA10: R64.2 ; off-sheet TTL10/MIPI_TX_CKP  [also labelled TTL10/MIPI_TX_CKP]
LCD_DATA11: R64.1 ; off-sheet TTL11/MIPI_TX_CKN  [also labelled TTL11/MIPI_TX_CKN]
LCD_DATA12: R66.4 ; off-sheet TTL12/MIPI_TX_D2P  [also labelled TTL12/MIPI_TX_D2P]
LCD_DATA13: R66.3 ; off-sheet TTL13/MIPI_TX_D2N  [also labelled TTL13/MIPI_TX_D2N]
LCD_DATA14: R66.2 ; off-sheet TTL14/MIPI_TX_D3P  [also labelled TTL14/MIPI_TX_D3P]
LCD_DATA15: R66.1 ; off-sheet TTL15/MIPI_TX_D3N  [also labelled TTL15/MIPI_TX_D3N]
LCD_DE: R69.1 ; off-sheet TTL27/LCD_DE  [also labelled TTL27/LCD_DE]
LCD_HSYNC: R67.1 ; off-sheet TTL25/LCD_HSYNC  [also labelled TTL25/LCD_HSYNC]
LCD_PCLK: R72.1 ; off-sheet TTL24/LCD_PCLK  [also labelled TTL24/LCD_PCLK]
LCD_PWM: J7.29 R70.2
LCD_RSTB: J7.31 R71.2
LCD_VSYNC: R68.1 ; off-sheet TTL26/LCD_VSYNC  [also labelled TTL26/LCD_VSYNC]
Panel_B3: J7.16 R64.8
Panel_B4: J7.17 R66.5
Panel_B5: J7.18 R66.6
Panel_B6: J7.19 R66.7
Panel_B7: J7.20 R66.8
Panel_DCLK: C38.2 J7.22 R72.2
Panel_DE: J7.27 R69.2
Panel_G2: J7.9 R65.6
Panel_G3: J7.10 R65.7
Panel_G4: J7.11 R65.8
Panel_G5: J7.12 R64.5
Panel_G6: J7.13 R64.6
Panel_G7: J7.14 R64.7
Panel_HS: J7.24 R67.2
Panel_R3: J7.3 R63.5
Panel_R4: J7.4 R63.6
Panel_R5: J7.5 R63.7
Panel_R6: J7.6 R63.8
Panel_R7: J7.7 R65.5
Panel_VS: J7.25 R68.2
RST#: D22.1(I/O2) J7.33 R73.2 R79.2
TP_SCL: D23.1(I/O2) J7.36 R74.2 R77.2
TP_SDA: D24.1(I/O2) J7.35 R75.2 R76.2

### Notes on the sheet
- LCD
- 22R电阻靠近主控
- TP
- (near R79) 22R电阻靠近主控

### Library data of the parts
C38 = C-0402: Part Number: C020102120018; Part Name: 贴片电容; Manufacture: 三星¦国巨¦村田; ERP Number: 1010200056; DSC1: ±0.25PF; DSC3: C0G; ID: 18; PCB Footprint: C0402L
D21-D24 = DI-ESD: as D12 on sheet P06 USB_SD
J7 = J-FPC05-40P: Part Number: J030105063856; Part Name: FPC座; DSC1: 40P; DSC2: 0.5mm间距; DSC3: 下接 抽拉式 卧贴; DSC4: H=2mm; DSC5: 镀锡; ID: 32
R63-R66 = RN_0402X4: Part Name: 贴片排阻; Part Number: C010302090004; ID: 4; DSC1: ±5%; DSC2: 1/16W
R67-R71 R76-R79 = R-0402: as R11 on sheet P06 USB_SD
R72 = R-0402: as R10 on sheet P06 USB_SD
R73 = R-0402: as R56 on sheet P07 ETHERNET
R74 R75 = R-0402: as R1 on sheet P04 POWER_SUPPLY

## Sheet P09 AUDIO.SchDoc
size 420 x 297 mm
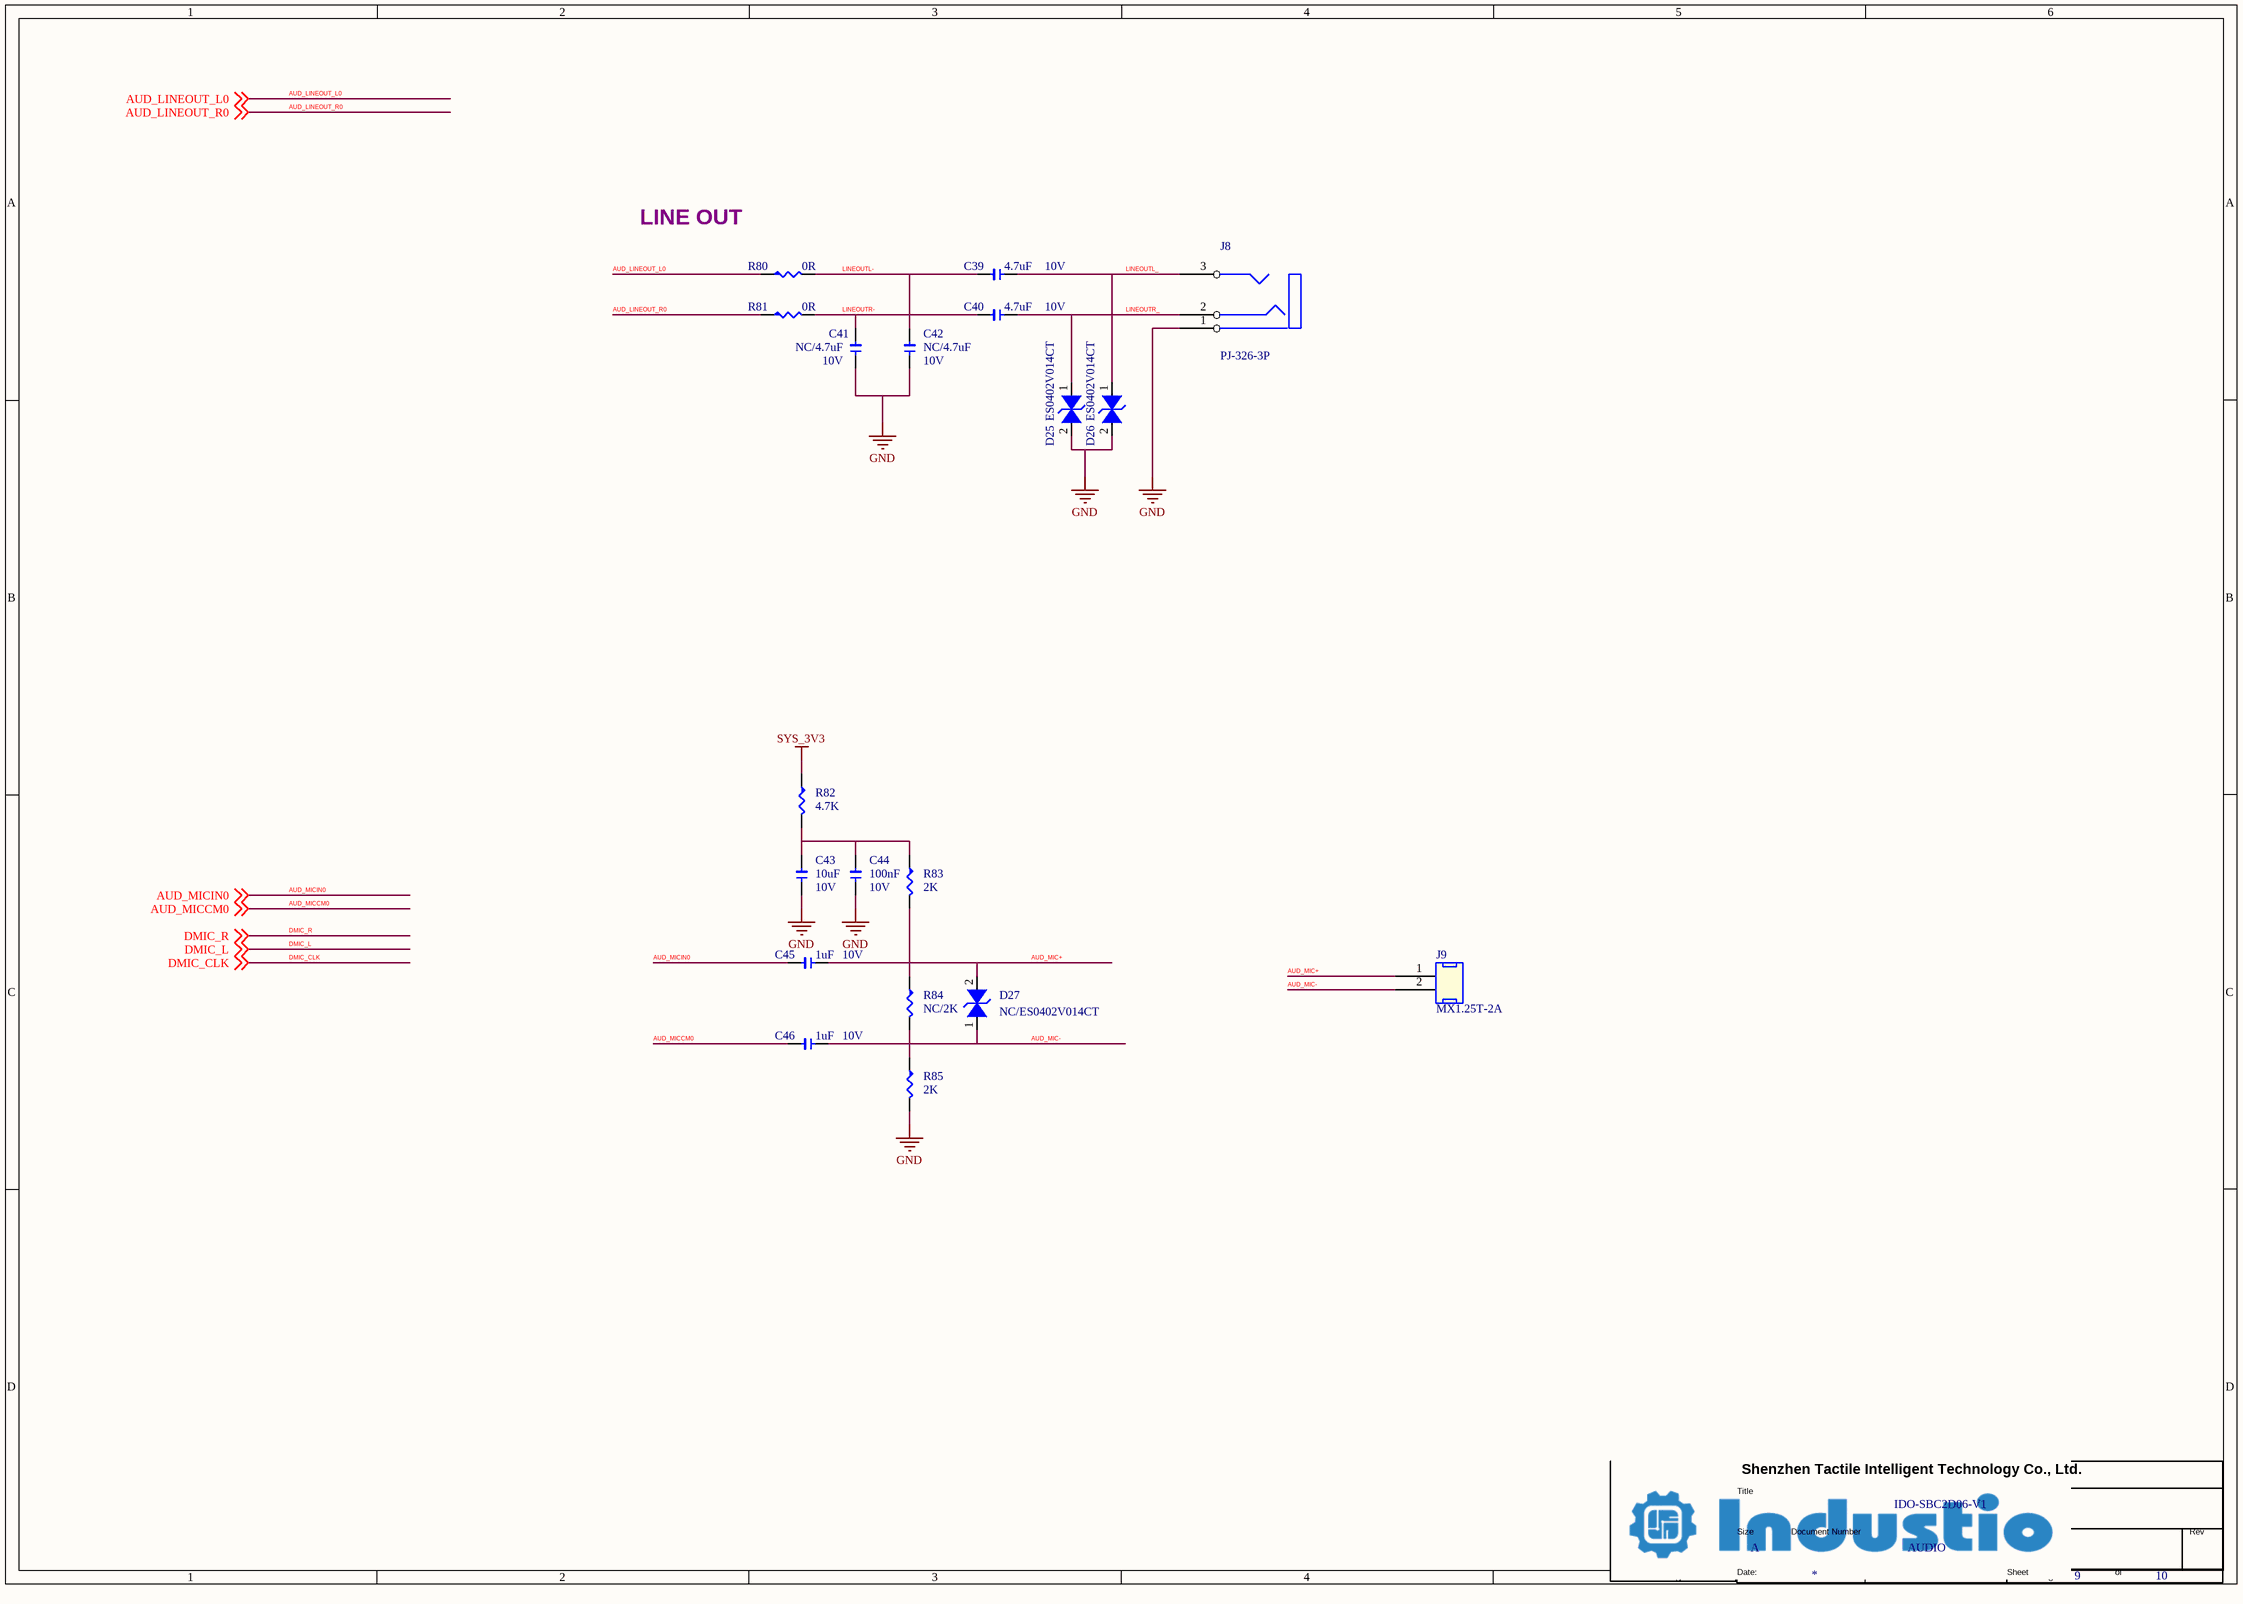
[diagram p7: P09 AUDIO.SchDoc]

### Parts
(Parts that share a designator on the sheet are numbered #1, #2 ... from top to bottom, then left to right.)
*#8  Page Count: 10  Page Number: 9  Page Size: A  Title: IDO-SBC2D06-V1  Doc: AUDIO  (hidden comment: TitleBlock1)  (graphical)
C39  4.7uF  DSC2: 10V  [1206]
C40  4.7uF  DSC2: 10V  [1206]
C41  NC/4.7uF  DSC2: 10V  [1206]
C42  NC/4.7uF  DSC2: 10V  [1206]
C43  10uF  DSC2: 10V  [1206]
C44  100nF  DSC2: 10V  [1206]
C45  1uF  DSC2: 10V  [1206]
C46  1uF  DSC2: 10V  [1206]
D25  ES0402V014CT  [V0402]
D26  ES0402V014CT  [V0402]
D27  NC/ES0402V014CT  [V0402]
J8  PJ-326-3P  [PJ-326A-3P]
J9  MX1.25T-2A  [MX125T-2A]
R80  0R  [R0402L]
R81  0R  [R0402L]
R82  4.7K  [R0402L]
R83  2K  [R0402L]
R84  NC/2K  [R0402L]
R85  2K  [R0402L]

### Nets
GND: C41.1 C42.1 C43.1 C44.1 D25.2(I/O1) D26.2(I/O1) J8.1(COM) R85.2
SYS_3V3: R82.1
AUD_LINEOUT_L0: R80.1 ; off-sheet AUD_LINEOUT_L0
AUD_LINEOUT_R0: R81.1 ; off-sheet AUD_LINEOUT_R0
AUD_MIC+: C45.1 D27.2(I/O1) J9.1 R83.2 R84.1
AUD_MIC-: C46.1 D27.1(I/O2) J9.2 R84.2 R85.1
AUD_MICCM0: C46.2 ; off-sheet AUD_MICCM0
AUD_MICIN0: C45.2 ; off-sheet AUD_MICIN0
LINEOUTL-: C39.2 C42.2 R80.2
LINEOUTL_: C39.1 D26.1(I/O2) J8.3(R)
LINEOUTR-: C40.2 C41.2 R81.2
LINEOUTR_: C40.1 D25.1(I/O2) J8.2(L)
NetC43_2: C43.2 C44.2 R82.2 R83.1

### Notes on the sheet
- LINE OUT

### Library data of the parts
C39 = C-0402: Manufacture: 三星¦国巨¦村田; Part Name: 贴片电容; Part Number: C020102120067; PCB Footprint: C0402L; ID: 67; DSC3: X5R; DSC1: ±20%
C40 C42 = C-0402: Part Number: C020102120067; Part Name: 贴片电容; Manufacture: 三星¦国巨¦村田; PCB Footprint: C0402L; DSC1: ±20%; DSC3: X5R; ID: 67
C41 = C-0402: Manufacture: 三星¦国巨¦村田; Part Name: 贴片电容; Part Number: C020102120067; ID: 67; DSC3: X5R; DSC1: ±20%; PCB Footprint: C0402L
C43 = C-0603: Part Number: C020102120071; Part Name: 贴片电容; Manufacture: 三星¦国巨¦村田; PCB Footprint: C0603L; ERP Number: 1010200076; DSC1: ±20%; DSC3: X5R; ID: 71
C44 = C-0402: Part Number: C020102120060; Part Name: 贴片电容; Manufacture: 三星¦国巨¦村田; PCB Footprint: C0402L; DSC1: ±10%; DSC3: X7R; ID: 60
C45 = C-0402: Manufacture: 三星¦国巨¦村田; Part Name: 贴片电容; Part Number: C020102120064; PCB Footprint: C0402L; ID: 64; DSC3: X5R; DSC1: ±10%; ERP Number: 1010200054
C46 = C-0402: Part Number: C020102120064; Part Name: 贴片电容; Manufacture: 三星¦国巨¦村田; PCB Footprint: C0402L; ERP Number: 1010200054; DSC1: ±10%; DSC3: X5R; ID: 64
D25 D26 = DI-ESD: as D1 on sheet P04 POWER_SUPPLY
D27 = DI-ESD: as D12 on sheet P06 USB_SD
J8 = J-PJ-326A-3P: Part Name: 音频耳机座; Part Number: J050502940003; P/N: 182K00300S; ID: 11; DSC2: 14*5.6*5.1mm; DSC1: 3.5mm贴片式耳机座 凸头 3P 双定位柱
J9 = J-H-2P: Part Number: J020110233936; ID: 50; DSC5: A1251WV-2P(CJT); DSC4: 米黄色胶壳 耐高温; DSC3: 通孔180度直针; DSC2: 1.25mm间距; DSC1: 2p
R80 R81 = R-0402: as R42 on sheet P07 ETHERNET
R82 = R-0402: as R1 on sheet P04 POWER_SUPPLY
R83-R85 = R-0402: Part Name: 贴片电阻; Part Number: C011002080774; ERP Number: 1010200328; DSC1: ±1%; DSC2: 1/16W; ID: 774

## Sheet P10 Debug_RS485_RS232.SchDoc
size 420 x 297 mm
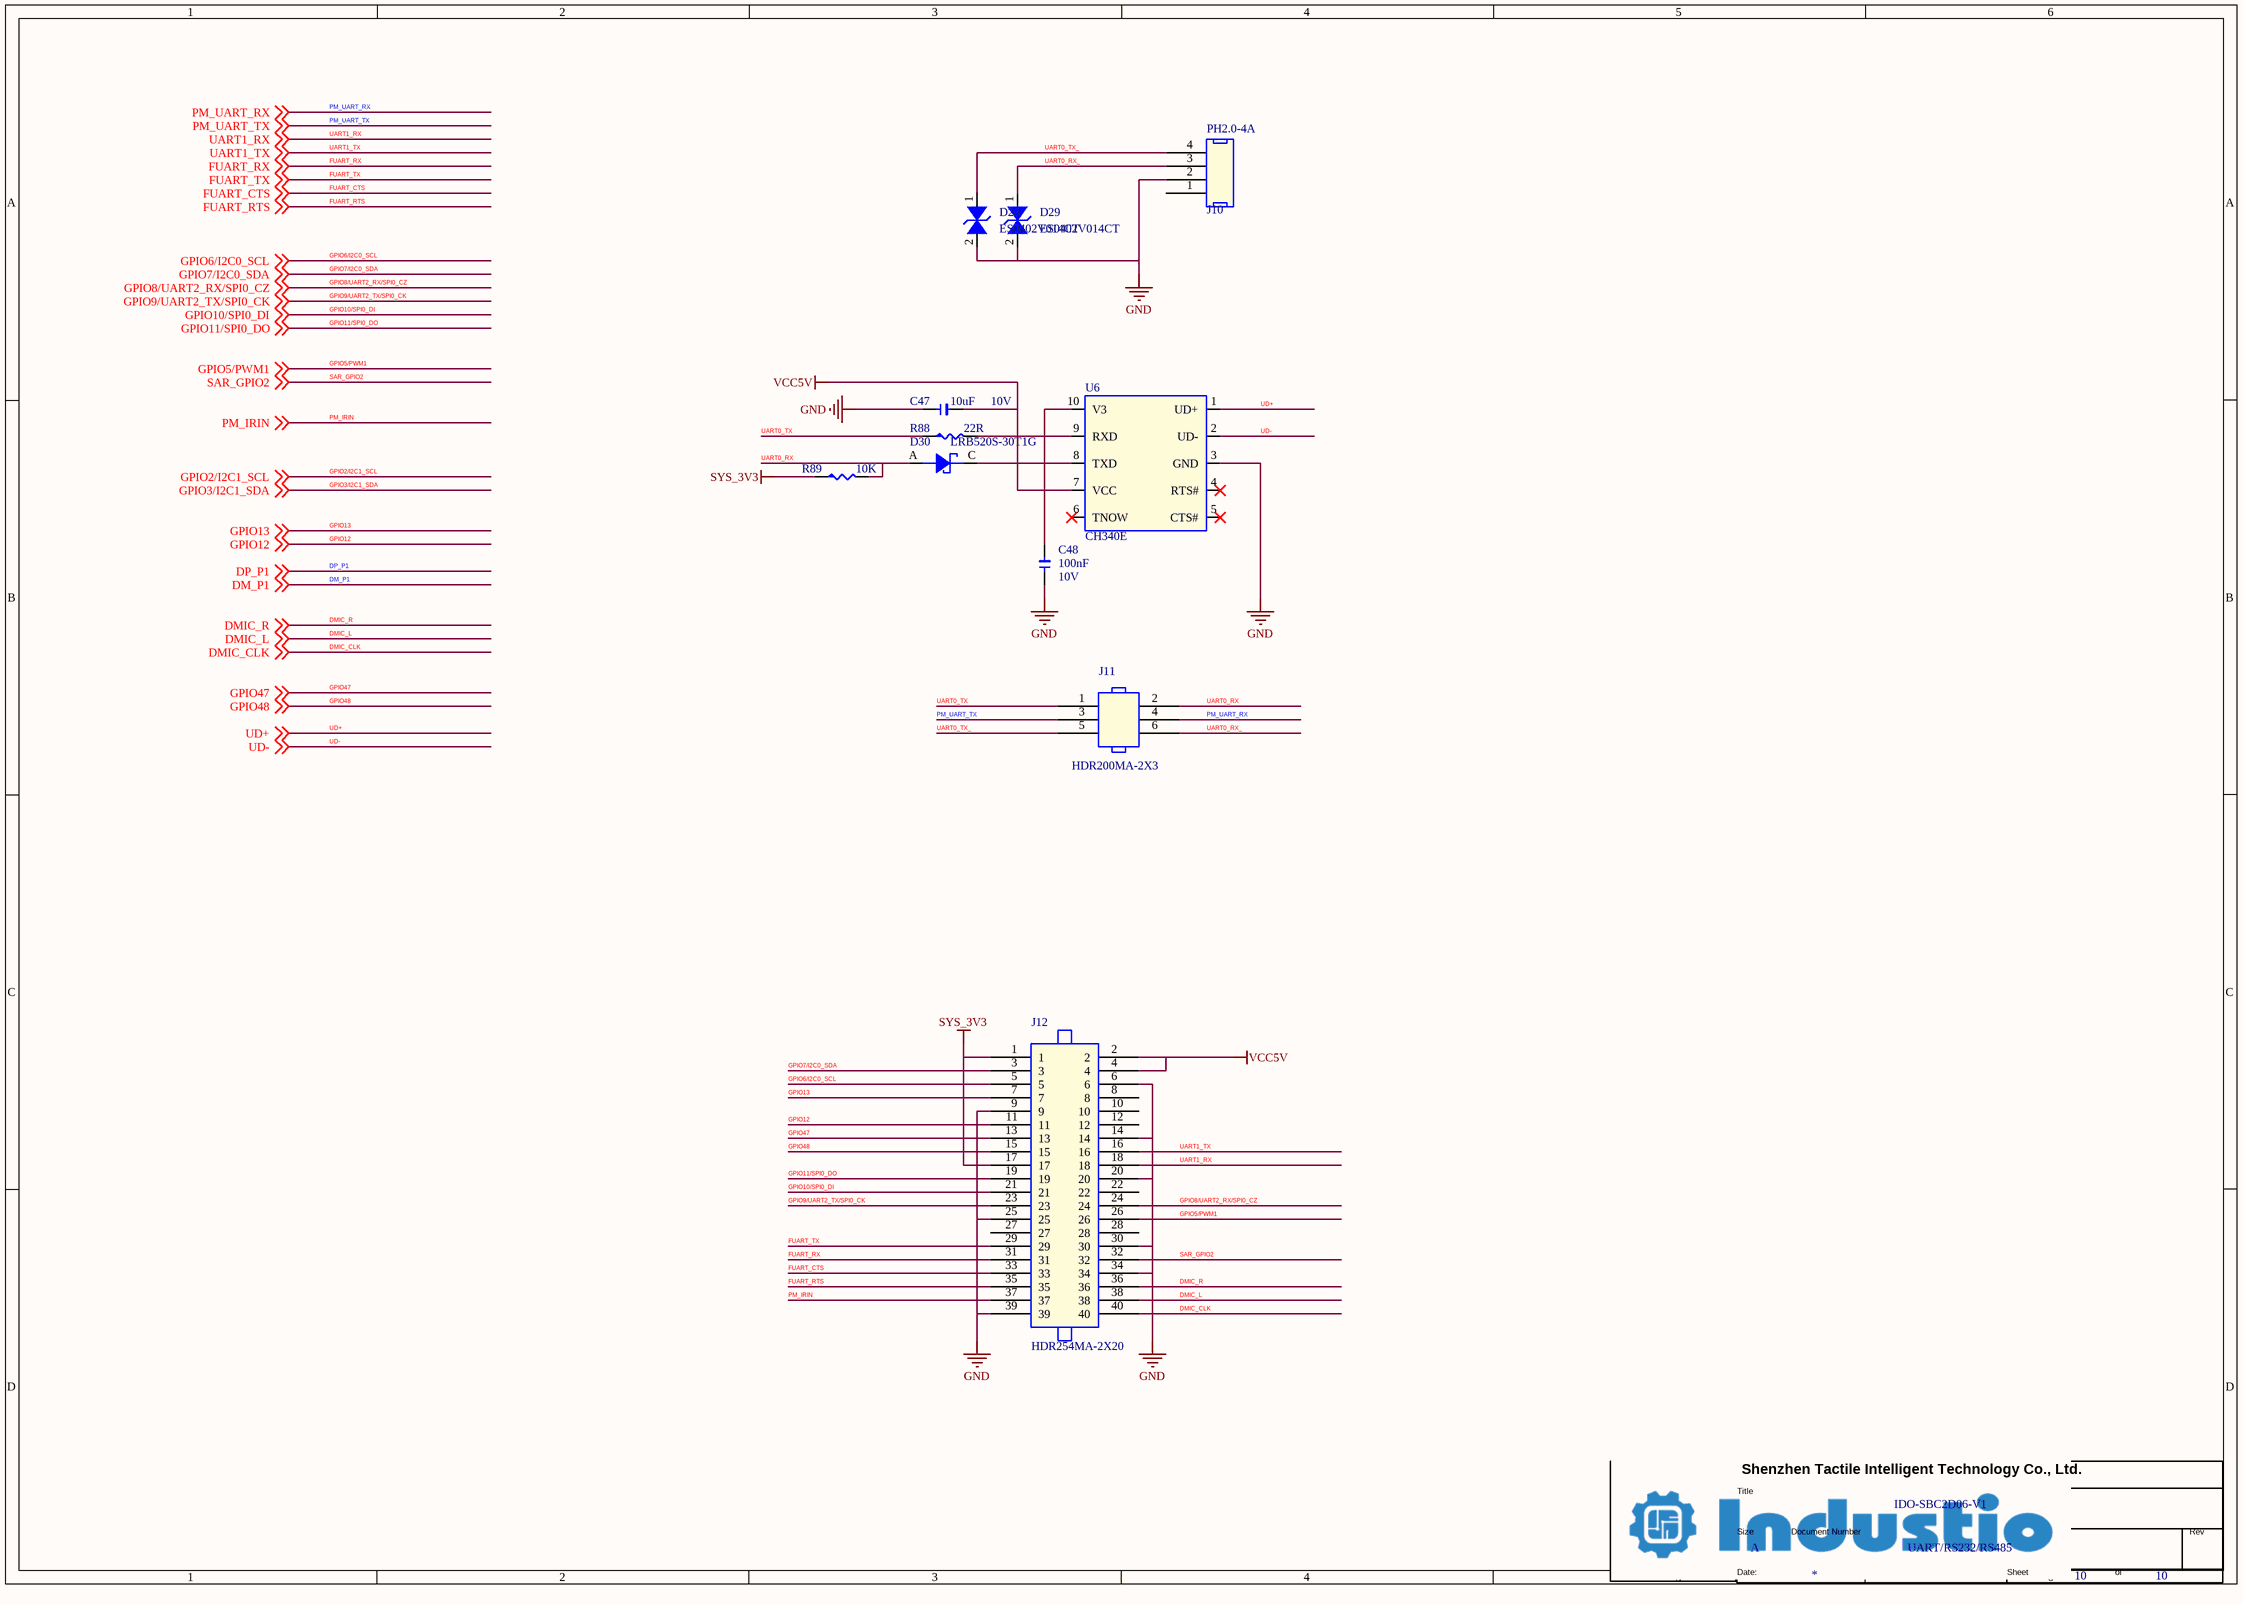
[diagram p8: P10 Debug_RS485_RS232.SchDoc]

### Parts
(Parts that share a designator on the sheet are numbered #1, #2 ... from top to bottom, then left to right.)
*#9  Page Count: 10  Page Size: A  Title: IDO-SBC2D06-V1  Doc: UART/RS232/RS485  (hidden comment: TitleBlock1)  (graphical)
C47  10uF  DSC2: 10V  [1206]
C48  100nF  DSC2: 10V  [1206]
D28  ES0402V014CT  [V0402]
D29  ES0402V014CT  [V0402]
D30  LRB520S-30T1G  [SOD523]
J10  PH2.0-4A  [PH200-4A]
J11  HDR200MA-2X3  [HDR200MA-2X3]
J12  HDR254MA-2X20  [HDR254MA-2X20]
R88  22R  [R0402L]
R89  10K  [R0402L]
U6  CH340E  [MSOP-10]

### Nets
GND: C47.1 C48.1 D28.2(I/O1) D29.2(I/O1) J10.2 J12.6 J12.9 J12.14 J12.20 J12.25 J12.30 J12.34 J12.39 U6.3(GND)
SYS_3V3: J12.1 J12.17 R89.1
VCC5V: C47.2 J12.2 J12.4 U6.7(VCC)
DMIC_CLK: J12.40 ; off-sheet DMIC_CLK
DMIC_L: J12.38 ; off-sheet DMIC_L
DMIC_R: J12.36 ; off-sheet DMIC_R
FUART_CTS: J12.33 ; off-sheet FUART_CTS
FUART_RTS: J12.35 ; off-sheet FUART_RTS
FUART_RX: J12.31 ; off-sheet FUART_RX
FUART_TX: J12.29 ; off-sheet FUART_TX
GPIO5/PWM1: J12.26 ; off-sheet GPIO5/PWM1
GPIO6/I2C0_SCL: J12.5 ; off-sheet GPIO6/I2C0_SCL
GPIO7/I2C0_SDA: J12.3 ; off-sheet GPIO7/I2C0_SDA
GPIO8/UART2_RX/SPI0_CZ: J12.24 ; off-sheet GPIO8/UART2_RX/SPI0_CZ
GPIO9/UART2_TX/SPI0_CK: J12.23 ; off-sheet GPIO9/UART2_TX/SPI0_CK
GPIO10/SPI0_DI: J12.21 ; off-sheet GPIO10/SPI0_DI
GPIO11/SPI0_DO: J12.19 ; off-sheet GPIO11/SPI0_DO
GPIO12: J12.11 ; off-sheet GPIO12
GPIO13: J12.7 ; off-sheet GPIO13
GPIO47: J12.13 ; off-sheet GPIO47
GPIO48: J12.15 ; off-sheet GPIO48
PM_IRIN: J12.37 ; off-sheet PM_IRIN
PM_UART_RX: J11.4 ; off-sheet PM_UART_RX
PM_UART_TX: J11.3 ; off-sheet PM_UART_TX
SAR_GPIO2: J12.32 ; off-sheet SAR_GPIO2
UART0_RX: D30.A J11.2 R89.2
UART0_RX_: D29.1(I/O2) J10.3 J11.6
UART0_TX: J11.1 R88.1
UART0_TX_: D28.1(I/O2) J10.4 J11.5
UART1_RX: J12.18 ; off-sheet UART1_RX
UART1_TX: J12.16 ; off-sheet UART1_TX
UD+: U6.1(UD+) ; off-sheet UD+
UD-: U6.2(UD-) ; off-sheet UD-
NetC48_2: C48.2 U6.10(V3)
NetD30_C: D30.C U6.8(TXD)
NetR88_2: R88.2 U6.9(RXD)

Not connected (* = marked no-connect by the designer): J10 1; J12 8 10 12 22 27 28; U6 4(RTS#)* 5(CTS#)* 6(TNOW)*

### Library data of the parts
C47 = C-0603: as C43 on sheet P09 AUDIO
C48 = C-0402: as C44 on sheet P09 AUDIO
D28 D29 = DI-ESD: as D12 on sheet P06 USB_SD
D30 = DI-XI-S: Part Number: C040202220002; Part Name: 肖特基二级管; Manufacture: 乐山无线电; CLASS: IC; DSC1: VR=30V; DSC2: IF=200mA; DSC3: VF=350mV/10mA; DSC4: IR=0.5uA; ID: 2; Solder: 推荐
J10 = J-H-4P: Part Name: PH; Part Number: J020302820003; ID: 13; DSC5: A2001WV-4P(CJT); DSC4: 米黄色胶壳 耐高温; DSC3: 通孔180度直针; DSC2: 2.0mm间距; DSC1: 4p
J11 = J-HDR-D-6: Part Name: 双排针; Part Number: J010102760002; ID: 2; DSC7: A2005WV-2x3P(CJT); DSC6: 黑胶; DSC5: 针长8.8mm  2.8+2(H塑高)+4 mm; DSC4: 通孔直针; DSC3: 2mm脚距; DSC2: 2x3; DSC1: 双排单塑
J12 = J-HDR-D-40: Part Number: J010104013835; Part Name: 双排针; DSC1: 双排单塑; DSC2: 2x20; DSC3: 2.54mm脚距; DSC4: 通孔直针; DSC5: 针长11.5mm 3+2.5(H塑高)+6mm; DSC6: 黑胶; DSC7: A2541WV-2x20P(CJT); ID: 64
R88 = R-0402: as R11 on sheet P06 USB_SD
R89 = R-0402: as R21 on sheet P06 USB_SD
U6 = U-CH340E_0: Part Number: C100202500006; Part Name: USB芯片; Manufacture: WCH(南京沁恒); ERP Number: 1010100113; DSC1: USB UART Bridge,Up to 2Mbps; DSC2: MSOP-10，0.5mm Pitch; DSC3: -20℃~+70℃; ID: 17

## Sheet P05 2D02.SchDoc
size 420 x 297 mm
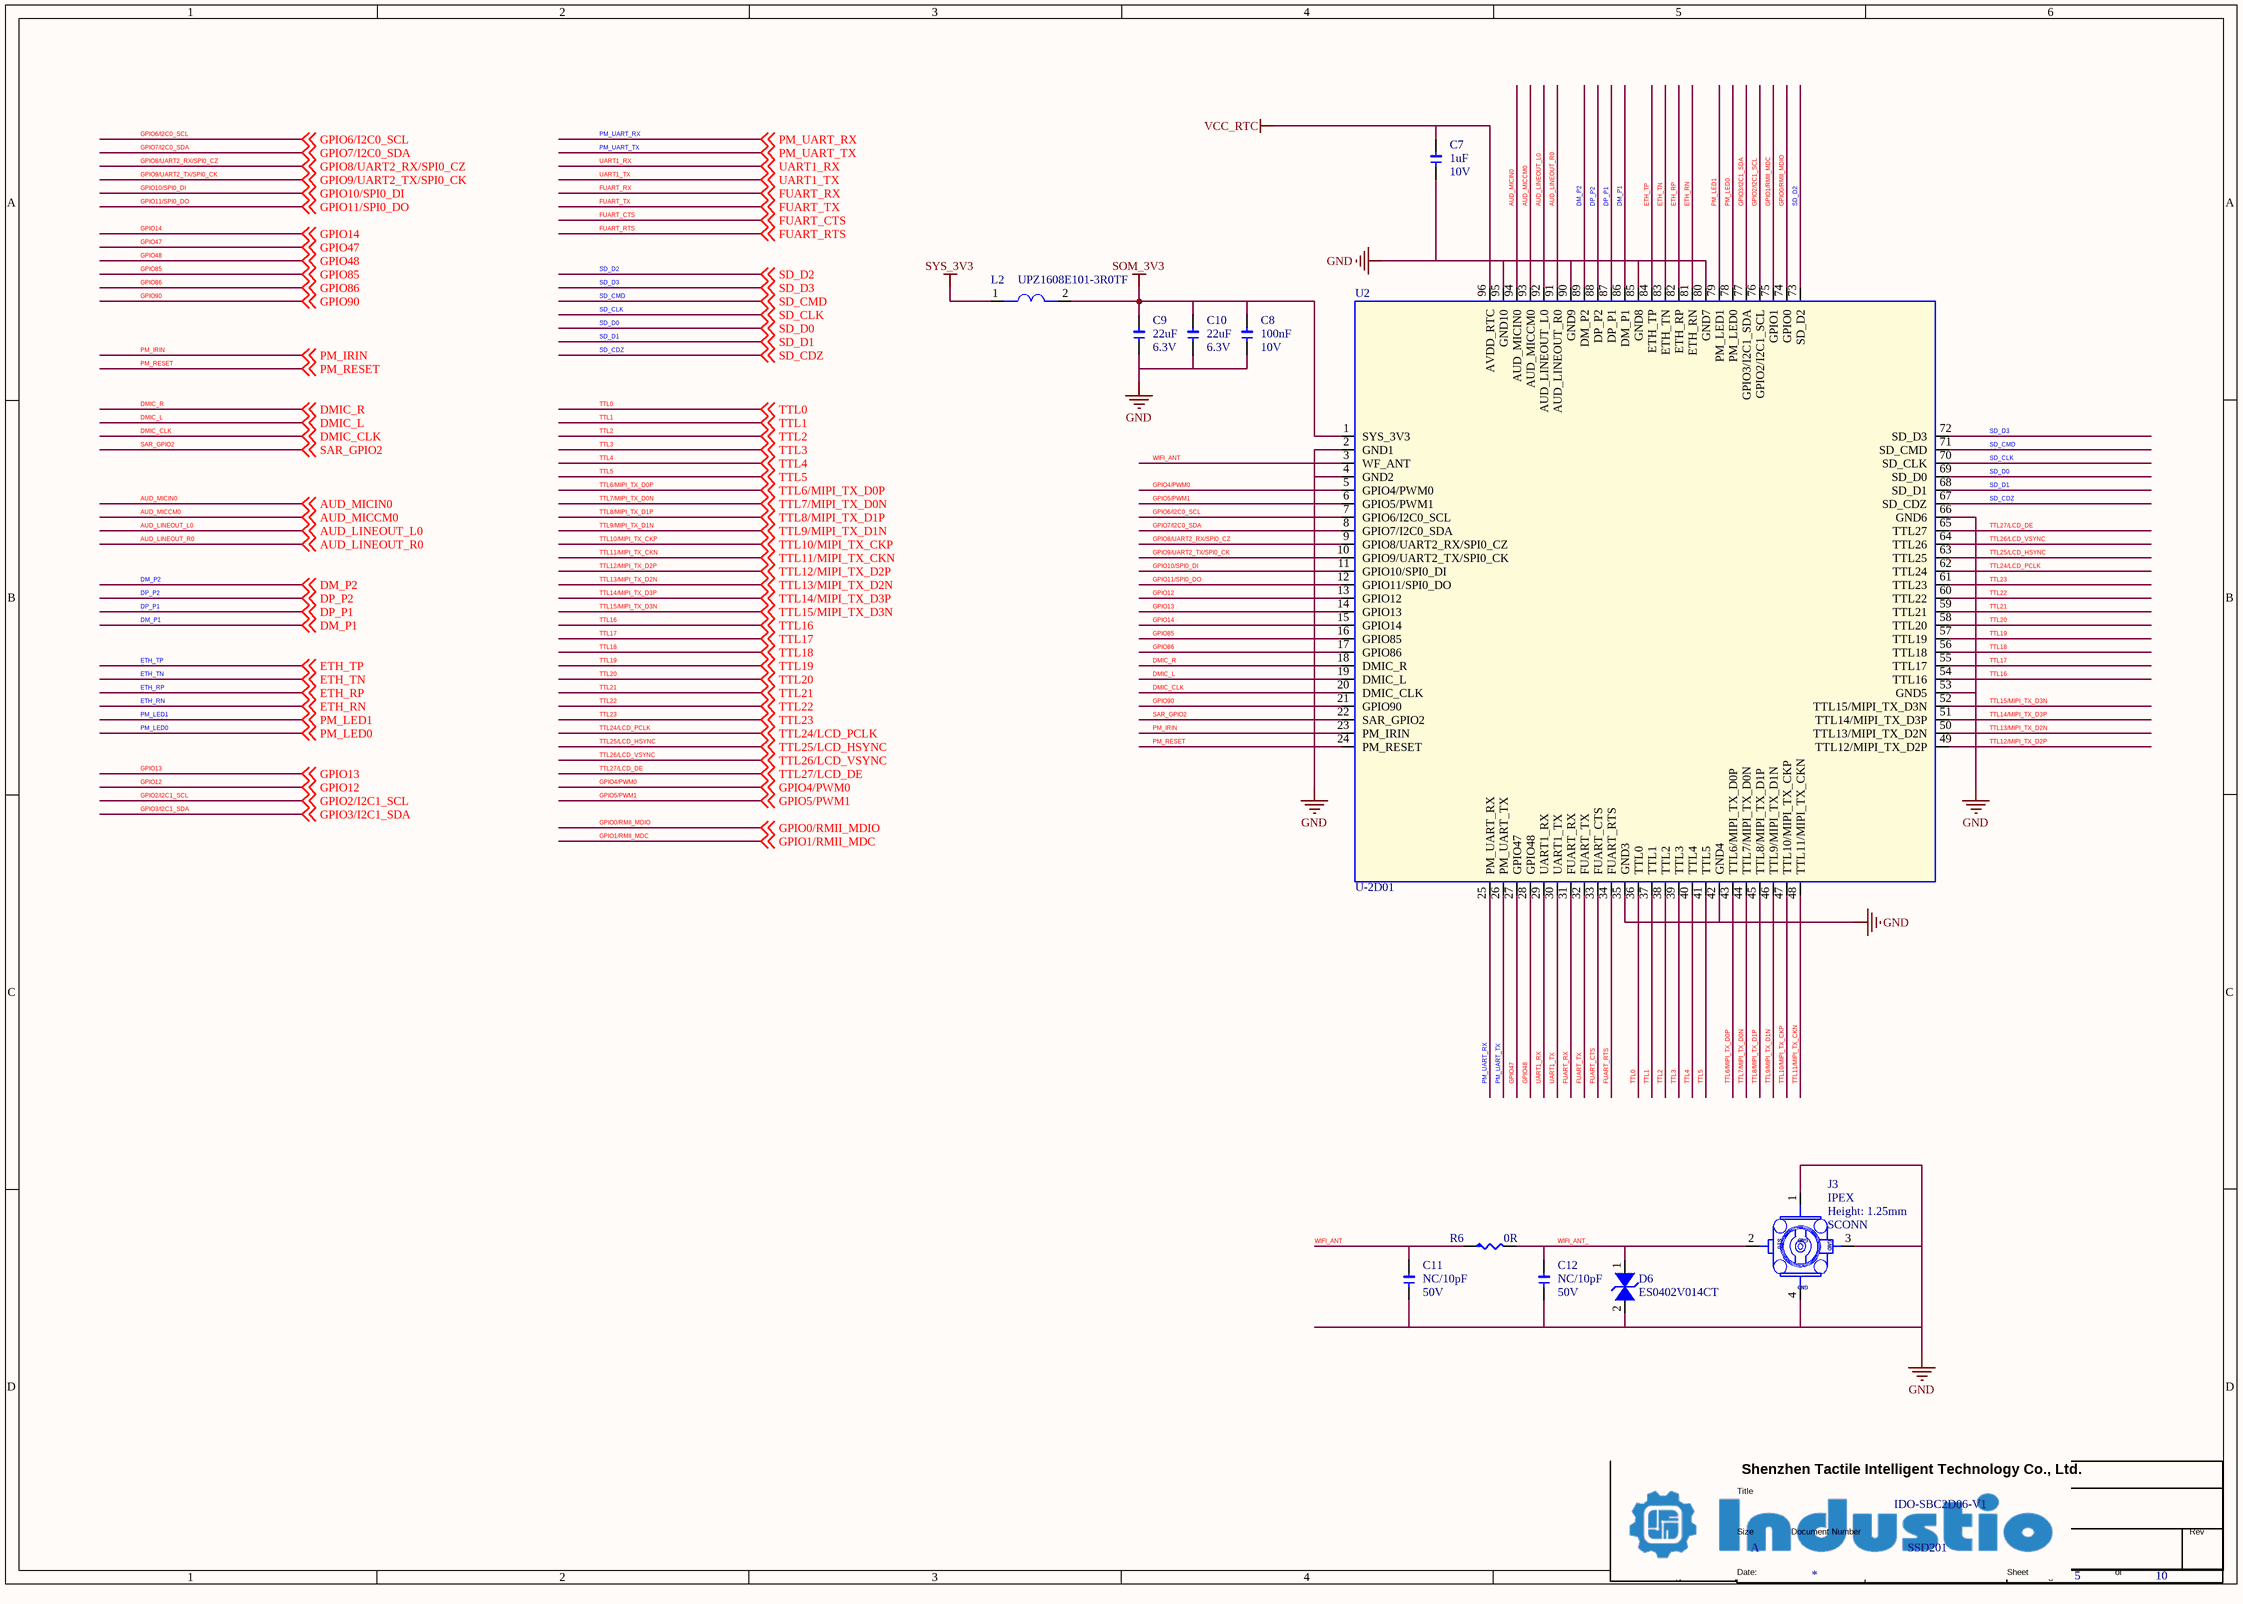
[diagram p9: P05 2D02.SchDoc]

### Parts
(Parts that share a designator on the sheet are numbered #1, #2 ... from top to bottom, then left to right.)
*#10  Page Count: 10  Page Number: 5  Page Size: A  Title: IDO-SBC2D06-V1  Doc: SSD201  (hidden comment: TitleBlock1)  (graphical)
C7  1uF  DSC2: 10V  [1206]
C8  100nF  DSC2: 10V  [1206]
C9  22uF  DSC2: 6.3V  [1206]
C10  22uF  DSC2: 6.3V  [1206]
C11  NC/10pF  DSC2: 50V  [1206]
C12  NC/10pF  DSC2: 50V  [1206]
D6  ES0402V014CT  [V0402]
J3  IPEX  Material: SCONN  Height: 1.25mm  [IPEX-20279-001E]
L2  UPZ1608E101-3R0TF  [L0603]
R6  0R  [R0402L]
U2  U-2D01  [IDO_2D01_LGA96]

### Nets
GND: C7.1 C8.1 C9.1 C10.1 C11.1 C12.1 D6.2(I/O1) J3.1(GND1) J3.3(GND2) J3.4(GND3) U2.2(GND1) U2.4(GND2) U2.35(GND3) U2.42(GND4) U2.53(GND5) U2.66(GND6) U2.80(GND7) U2.85(GND8) U2.90(GND9) U2.95(GND10)
SOM_3V3: C8.2 C9.2 C10.2 L2.2 U2.1(SYS_3V3)
SYS_3V3: L2.1
VCC_RTC: C7.2 U2.96(AVDD_RTC)
AUD_LINEOUT_L0: U2.92(AUD_LINEOUT_L0) ; off-sheet AUD_LINEOUT_L0
AUD_LINEOUT_R0: U2.91(AUD_LINEOUT_R0) ; off-sheet AUD_LINEOUT_R0
AUD_MICCM0: U2.93(AUD_MICCM0) ; off-sheet AUD_MICCM0
AUD_MICIN0: U2.94(AUD_MICIN0) ; off-sheet AUD_MICIN0
DM_P1: U2.86(DM_P1) ; off-sheet DM_P1
DM_P2: U2.89(DM_P2) ; off-sheet DM_P2
DMIC_CLK: U2.20(DMIC_CLK) ; off-sheet DMIC_CLK
DMIC_L: U2.19(DMIC_L) ; off-sheet DMIC_L
DMIC_R: U2.18(DMIC_R) ; off-sheet DMIC_R
DP_P1: U2.87(DP_P1) ; off-sheet DP_P1
DP_P2: U2.88(DP_P2) ; off-sheet DP_P2
ETH_RN: U2.81(ETH_RN) ; off-sheet ETH_RN
ETH_RP: U2.82(ETH_RP) ; off-sheet ETH_RP
ETH_TN: U2.83(ETH_TN) ; off-sheet ETH_TN
ETH_TP: U2.84(ETH_TP) ; off-sheet ETH_TP
FUART_CTS: U2.33(FUART_CTS) ; off-sheet FUART_CTS
FUART_RTS: U2.34(FUART_RTS) ; off-sheet FUART_RTS
FUART_RX: U2.31(FUART_RX) ; off-sheet FUART_RX
FUART_TX: U2.32(FUART_TX) ; off-sheet FUART_TX
GPIO0/RMII_MDIO: U2.74(GPIO0) ; off-sheet GPIO0/RMII_MDIO
GPIO1/RMII_MDC: U2.75(GPIO1) ; off-sheet GPIO1/RMII_MDC
GPIO2/I2C1_SCL: U2.76(GPIO2/I2C1_SCL) ; off-sheet GPIO2/I2C1_SCL
GPIO3/I2C1_SDA: U2.77(GPIO3/I2C1_SDA) ; off-sheet GPIO3/I2C1_SDA
GPIO4/PWM0: U2.5(GPIO4/PWM0) ; off-sheet GPIO4/PWM0
GPIO5/PWM1: U2.6(GPIO5/PWM1) ; off-sheet GPIO5/PWM1
GPIO6/I2C0_SCL: U2.7(GPIO6/I2C0_SCL) ; off-sheet GPIO6/I2C0_SCL
GPIO7/I2C0_SDA: U2.8(GPIO7/I2C0_SDA) ; off-sheet GPIO7/I2C0_SDA
GPIO8/UART2_RX/SPI0_CZ: U2.9(GPIO8/UART2_RX/SPI0_CZ) ; off-sheet GPIO8/UART2_RX/SPI0_CZ
GPIO9/UART2_TX/SPI0_CK: U2.10(GPIO9/UART2_TX/SPI0_CK) ; off-sheet GPIO9/UART2_TX/SPI0_CK
GPIO10/SPI0_DI: U2.11(GPIO10/SPI0_DI) ; off-sheet GPIO10/SPI0_DI
GPIO11/SPI0_DO: U2.12(GPIO11/SPI0_DO) ; off-sheet GPIO11/SPI0_DO
GPIO12: U2.13(GPIO12) ; off-sheet GPIO12
GPIO13: U2.14(GPIO13) ; off-sheet GPIO13
GPIO14: U2.15(GPIO14) ; off-sheet GPIO14
GPIO47: U2.27(GPIO47) ; off-sheet GPIO47
GPIO48: U2.28(GPIO48) ; off-sheet GPIO48
GPIO85: U2.16(GPIO85) ; off-sheet GPIO85
GPIO86: U2.17(GPIO86) ; off-sheet GPIO86
GPIO90: U2.21(GPIO90) ; off-sheet GPIO90
PM_IRIN: U2.23(PM_IRIN) ; off-sheet PM_IRIN
PM_LED0: U2.78(PM_LED0) ; off-sheet PM_LED0
PM_LED1: U2.79(PM_LED1) ; off-sheet PM_LED1
PM_RESET: U2.24(PM_RESET) ; off-sheet PM_RESET
PM_UART_RX: U2.25(PM_UART_RX) ; off-sheet PM_UART_RX
PM_UART_TX: U2.26(PM_UART_TX) ; off-sheet PM_UART_TX
SAR_GPIO2: U2.22(SAR_GPIO2) ; off-sheet SAR_GPIO2
SD_CDZ: U2.67(SD_CDZ) ; off-sheet SD_CDZ
SD_CLK: U2.70(SD_CLK) ; off-sheet SD_CLK
SD_CMD: U2.71(SD_CMD) ; off-sheet SD_CMD
SD_D0: U2.69(SD_D0) ; off-sheet SD_D0
SD_D1: U2.68(SD_D1) ; off-sheet SD_D1
SD_D2: U2.73(SD_D2) ; off-sheet SD_D2
SD_D3: U2.72(SD_D3) ; off-sheet SD_D3
TTL0: U2.36(TTL0) ; off-sheet TTL0  [project net LCD_DATA0]
TTL1: U2.37(TTL1) ; off-sheet TTL1  [project net LCD_DATA1]
TTL2: U2.38(TTL2) ; off-sheet TTL2  [project net LCD_DATA2]
TTL3: U2.39(TTL3) ; off-sheet TTL3  [project net LCD_DATA3]
TTL4: U2.40(TTL4) ; off-sheet TTL4  [project net LCD_DATA4]
TTL5: U2.41(TTL5) ; off-sheet TTL5  [project net LCD_DATA5]
TTL6/MIPI_TX_D0P: U2.43(TTL6/MIPI_TX_D0P) ; off-sheet TTL6/MIPI_TX_D0P  [project net LCD_DATA6]
TTL7/MIPI_TX_D0N: U2.44(TTL7/MIPI_TX_D0N) ; off-sheet TTL7/MIPI_TX_D0N  [project net LCD_DATA7]
TTL8/MIPI_TX_D1P: U2.45(TTL8/MIPI_TX_D1P) ; off-sheet TTL8/MIPI_TX_D1P  [project net LCD_DATA8]
TTL9/MIPI_TX_D1N: U2.46(TTL9/MIPI_TX_D1N) ; off-sheet TTL9/MIPI_TX_D1N  [project net LCD_DATA9]
TTL10/MIPI_TX_CKP: U2.47(TTL10/MIPI_TX_CKP) ; off-sheet TTL10/MIPI_TX_CKP  [project net LCD_DATA10]
TTL11/MIPI_TX_CKN: U2.48(TTL11/MIPI_TX_CKN) ; off-sheet TTL11/MIPI_TX_CKN  [project net LCD_DATA11]
TTL12/MIPI_TX_D2P: U2.49(TTL12/MIPI_TX_D2P) ; off-sheet TTL12/MIPI_TX_D2P  [project net LCD_DATA12]
TTL13/MIPI_TX_D2N: U2.50(TTL13/MIPI_TX_D2N) ; off-sheet TTL13/MIPI_TX_D2N  [project net LCD_DATA13]
TTL14/MIPI_TX_D3P: U2.51(TTL14/MIPI_TX_D3P) ; off-sheet TTL14/MIPI_TX_D3P  [project net LCD_DATA14]
TTL15/MIPI_TX_D3N: U2.52(TTL15/MIPI_TX_D3N) ; off-sheet TTL15/MIPI_TX_D3N  [project net LCD_DATA15]
TTL16: U2.54(TTL16) ; off-sheet TTL16
TTL17: U2.55(TTL17) ; off-sheet TTL17
TTL18: U2.56(TTL18) ; off-sheet TTL18
TTL19: U2.57(TTL19) ; off-sheet TTL19
TTL20: U2.58(TTL20) ; off-sheet TTL20
TTL21: U2.59(TTL21) ; off-sheet TTL21
TTL22: U2.60(TTL22) ; off-sheet TTL22
TTL23: U2.61(TTL23) ; off-sheet TTL23
TTL24/LCD_PCLK: U2.62(TTL24) ; off-sheet TTL24/LCD_PCLK  [project net LCD_PCLK]
TTL25/LCD_HSYNC: U2.63(TTL25) ; off-sheet TTL25/LCD_HSYNC  [project net LCD_HSYNC]
TTL26/LCD_VSYNC: U2.64(TTL26) ; off-sheet TTL26/LCD_VSYNC  [project net LCD_VSYNC]
TTL27/LCD_DE: U2.65(TTL27) ; off-sheet TTL27/LCD_DE  [project net LCD_DE]
UART1_RX: U2.29(UART1_RX) ; off-sheet UART1_RX
UART1_TX: U2.30(UART1_TX) ; off-sheet UART1_TX
WIFI_ANT: C11.2 R6.1 U2.3(WF_ANT)
WIFI_ANT_: C12.2 D6.1(I/O2) J3.2(SIG) R6.2

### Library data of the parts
C7 = C-0402: as C46 on sheet P09 AUDIO
C8 = C-0402: Manufacture: 三星¦国巨¦村田; Part Name: 贴片电容; Part Number: C020102120060; PCB Footprint: C0402L; ID: 60; DSC3: X7R; DSC1: ±10%
C9 C10 = C-0603: Manufacture: 三星¦国巨¦村田; Part Name: 贴片电容; Part Number: C020102120072; PCB Footprint: C0603L; ID: 72; DSC3: X5R; DSC1: ±20%; ERP Number: 1010200133
C11 C12 = C-0402: Manufacture: 三星¦国巨¦村田; Part Name: 贴片电容; Part Number: C020102120021; ID: 21; DSC3: C0G; DSC1: ±5%; ERP Number: 1010200151; PCB Footprint: C0402L
D6 = DI-ESD: as D12 on sheet P06 USB_SD
J3 = RF-IPEX-20279: SMD micro Coaxial Connector Receptacle vertial; Part Number: J110103040001; Part Name: IPEX座; Pack_Type: MHF-20279; DSC1: IPEX-20279-001E-01 板端贴片天线座 U.LF接头; DSC2: 贴片; ID: 1
L2 = FB-0603: as L4 on sheet P07 ETHERNET
R6 = R-0402: as R42 on sheet P07 ETHERNET
U2 = U-2D01_1

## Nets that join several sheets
GND: P04 POWER_SUPPLY (13 pins), P06 USB_SD (25 pins), P07 ETHERNET (25 pins), P08 LCD_TP (17 pins), P09 AUDIO (8 pins), P10 Debug_RS485_RS232 (14 pins), P05 2D02 (20 pins)
GND_EARTH: P04 POWER_SUPPLY (8 pins), P06 USB_SD (J5.5 J5.6 J5.7), P07 ETHERNET (8 pins)
SYS_3V3: P04 POWER_SUPPLY (9 pins), P06 USB_SD (7 pins), P07 ETHERNET (5 pins), P08 LCD_TP (5 pins), P09 AUDIO (R82.1), P10 Debug_RS485_RS232 (J12.1 J12.17 R89.1), P05 2D02 (L2.1)
VCC5V: P04 POWER_SUPPLY (6 pins), P06 USB_SD (C19.2 U3.5), P08 LCD_TP (J7.39 J7.40), P10 Debug_RS485_RS232 (C47.2 J12.2 J12.4 U6.7)
VCC_RTC: P04 POWER_SUPPLY (D4.C D5.C), P05 2D02 (C7.2 U2.96)
AUD_LINEOUT_L0: P09 AUDIO (R80.1), P05 2D02 (U2.92)
AUD_LINEOUT_R0: P09 AUDIO (R81.1), P05 2D02 (U2.91)
AUD_MICCM0: P09 AUDIO (C46.2), P05 2D02 (U2.93)
AUD_MICIN0: P09 AUDIO (C45.2), P05 2D02 (U2.94)
DM_P2: P06 USB_SD (R12.1), P05 2D02 (U2.89)
DMIC_CLK: P10 Debug_RS485_RS232 (J12.40), P05 2D02 (U2.20)
DMIC_L: P10 Debug_RS485_RS232 (J12.38), P05 2D02 (U2.19)
DMIC_R: P10 Debug_RS485_RS232 (J12.36), P05 2D02 (U2.18)
DP_P2: P06 USB_SD (R14.1), P05 2D02 (U2.88)
ETH_RN: P07 ETHERNET (R27.1), P05 2D02 (U2.81)
ETH_RP: P07 ETHERNET (R26.1), P05 2D02 (U2.82)
ETH_TN: P07 ETHERNET (R25.1), P05 2D02 (U2.83)
ETH_TP: P07 ETHERNET (R23.1), P05 2D02 (U2.84)
FUART_CTS: P10 Debug_RS485_RS232 (J12.33), P05 2D02 (U2.33)
FUART_RTS: P10 Debug_RS485_RS232 (J12.35), P05 2D02 (U2.34)
FUART_RX: P10 Debug_RS485_RS232 (J12.31), P05 2D02 (U2.31)
FUART_TX: P10 Debug_RS485_RS232 (J12.29), P05 2D02 (U2.32)
GPIO0/RMII_MDIO: P07 ETHERNET (R40.1), P05 2D02 (U2.74)
GPIO1/RMII_MDC: P07 ETHERNET (R41.1), P05 2D02 (U2.75)
GPIO2/I2C1_SCL: P08 LCD_TP (R77.1), P05 2D02 (U2.76)
GPIO3/I2C1_SDA: P08 LCD_TP (R76.1), P05 2D02 (U2.77)
GPIO4/PWM0: P08 LCD_TP (R70.1), P05 2D02 (U2.5)
GPIO5/PWM1: P10 Debug_RS485_RS232 (J12.26), P05 2D02 (U2.6)
GPIO6/I2C0_SCL: P10 Debug_RS485_RS232 (J12.5), P05 2D02 (U2.7)
GPIO7/I2C0_SDA: P10 Debug_RS485_RS232 (J12.3), P05 2D02 (U2.8)
GPIO8/UART2_RX/SPI0_CZ: P10 Debug_RS485_RS232 (J12.24), P05 2D02 (U2.9)
GPIO9/UART2_TX/SPI0_CK: P10 Debug_RS485_RS232 (J12.23), P05 2D02 (U2.10)
GPIO10/SPI0_DI: P10 Debug_RS485_RS232 (J12.21), P05 2D02 (U2.11)
GPIO11/SPI0_DO: P10 Debug_RS485_RS232 (J12.19), P05 2D02 (U2.12)
GPIO12: P08 LCD_TP (R79.1), P10 Debug_RS485_RS232 (J12.11), P05 2D02 (U2.13)
GPIO13: P08 LCD_TP (R78.1), P10 Debug_RS485_RS232 (J12.7), P05 2D02 (U2.14)
GPIO14: P06 USB_SD (R19.1), P05 2D02 (U2.15)
GPIO47: P10 Debug_RS485_RS232 (J12.13), P05 2D02 (U2.27)
GPIO48: P10 Debug_RS485_RS232 (J12.15), P05 2D02 (U2.28)
GPIO85: P04 POWER_SUPPLY (LED1.C), P05 2D02 (U2.16)
GPIO86: P08 LCD_TP (R71.1), P05 2D02 (U2.17)
GPIO90: P06 USB_SD (R21.1), P05 2D02 (U2.21)
LCD_DATA0: P08 LCD_TP (R63.4), P05 2D02 (U2.36)
LCD_DATA1: P08 LCD_TP (R63.3), P05 2D02 (U2.37)
LCD_DATA2: P08 LCD_TP (R63.2), P05 2D02 (U2.38)
LCD_DATA3: P08 LCD_TP (R63.1), P05 2D02 (U2.39)
LCD_DATA4: P08 LCD_TP (R65.4), P05 2D02 (U2.40)
LCD_DATA5: P08 LCD_TP (R65.3), P05 2D02 (U2.41)
LCD_DATA6: P08 LCD_TP (R65.2), P05 2D02 (U2.43)
LCD_DATA7: P08 LCD_TP (R65.1), P05 2D02 (U2.44)
LCD_DATA8: P08 LCD_TP (R64.4), P05 2D02 (U2.45)
LCD_DATA9: P08 LCD_TP (R64.3), P05 2D02 (U2.46)
LCD_DATA10: P08 LCD_TP (R64.2), P05 2D02 (U2.47)
LCD_DATA11: P08 LCD_TP (R64.1), P05 2D02 (U2.48)
LCD_DATA12: P08 LCD_TP (R66.4), P05 2D02 (U2.49)
LCD_DATA13: P08 LCD_TP (R66.3), P05 2D02 (U2.50)
LCD_DATA14: P08 LCD_TP (R66.2), P05 2D02 (U2.51)
LCD_DATA15: P08 LCD_TP (R66.1), P05 2D02 (U2.52)
LCD_DE: P08 LCD_TP (R69.1), P05 2D02 (U2.65)
LCD_HSYNC: P08 LCD_TP (R67.1), P05 2D02 (U2.63)
LCD_PCLK: P08 LCD_TP (R72.1), P05 2D02 (U2.62)
LCD_VSYNC: P08 LCD_TP (R68.1), P05 2D02 (U2.64)
PM_IRIN: P10 Debug_RS485_RS232 (J12.37), P05 2D02 (U2.23)
PM_LED0: P07 ETHERNET (R31.1), P05 2D02 (U2.78)
PM_LED1: P07 ETHERNET (R29.1), P05 2D02 (U2.79)
PM_RESET: P04 POWER_SUPPLY (D3.1 SW1.3), P05 2D02 (U2.24)
PM_UART_RX: P10 Debug_RS485_RS232 (J11.4), P05 2D02 (U2.25)
PM_UART_TX: P10 Debug_RS485_RS232 (J11.3), P05 2D02 (U2.26)
SAR_GPIO2: P10 Debug_RS485_RS232 (J12.32), P05 2D02 (U2.22)
SD_CDZ: P06 USB_SD (R17.1), P05 2D02 (U2.67)
SD_CLK: P06 USB_SD (R18.1), P05 2D02 (U2.70)
SD_CMD: P06 USB_SD (R16.1), P05 2D02 (U2.71)
SD_D0: P06 USB_SD (R10.1), P05 2D02 (U2.69)
SD_D1: P06 USB_SD (R11.1), P05 2D02 (U2.68)
SD_D2: P06 USB_SD (R13.1), P05 2D02 (U2.73)
SD_D3: P06 USB_SD (R15.1), P05 2D02 (U2.72)
TTL16: P07 ETHERNET (R51.1), P05 2D02 (U2.54)
TTL17: P07 ETHERNET (R49.1), P05 2D02 (U2.55)
TTL18: P07 ETHERNET (R48.1), P05 2D02 (U2.56)
TTL19: P07 ETHERNET (R50.1), P05 2D02 (U2.57)
TTL20: P07 ETHERNET (R47.1), P05 2D02 (U2.58)
TTL21: P07 ETHERNET (R43.1), P05 2D02 (U2.59)
TTL22: P07 ETHERNET (R44.1), P05 2D02 (U2.60)
TTL23: P07 ETHERNET (R45.1), P05 2D02 (U2.61)
UART1_RX: P10 Debug_RS485_RS232 (J12.18), P05 2D02 (U2.29)
UART1_TX: P10 Debug_RS485_RS232 (J12.16), P05 2D02 (U2.30)
UD+: P04 POWER_SUPPLY (D2.1 J1.3), P10 Debug_RS485_RS232 (U6.1)
UD-: P04 POWER_SUPPLY (D1.1 J1.2), P10 Debug_RS485_RS232 (U6.2)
